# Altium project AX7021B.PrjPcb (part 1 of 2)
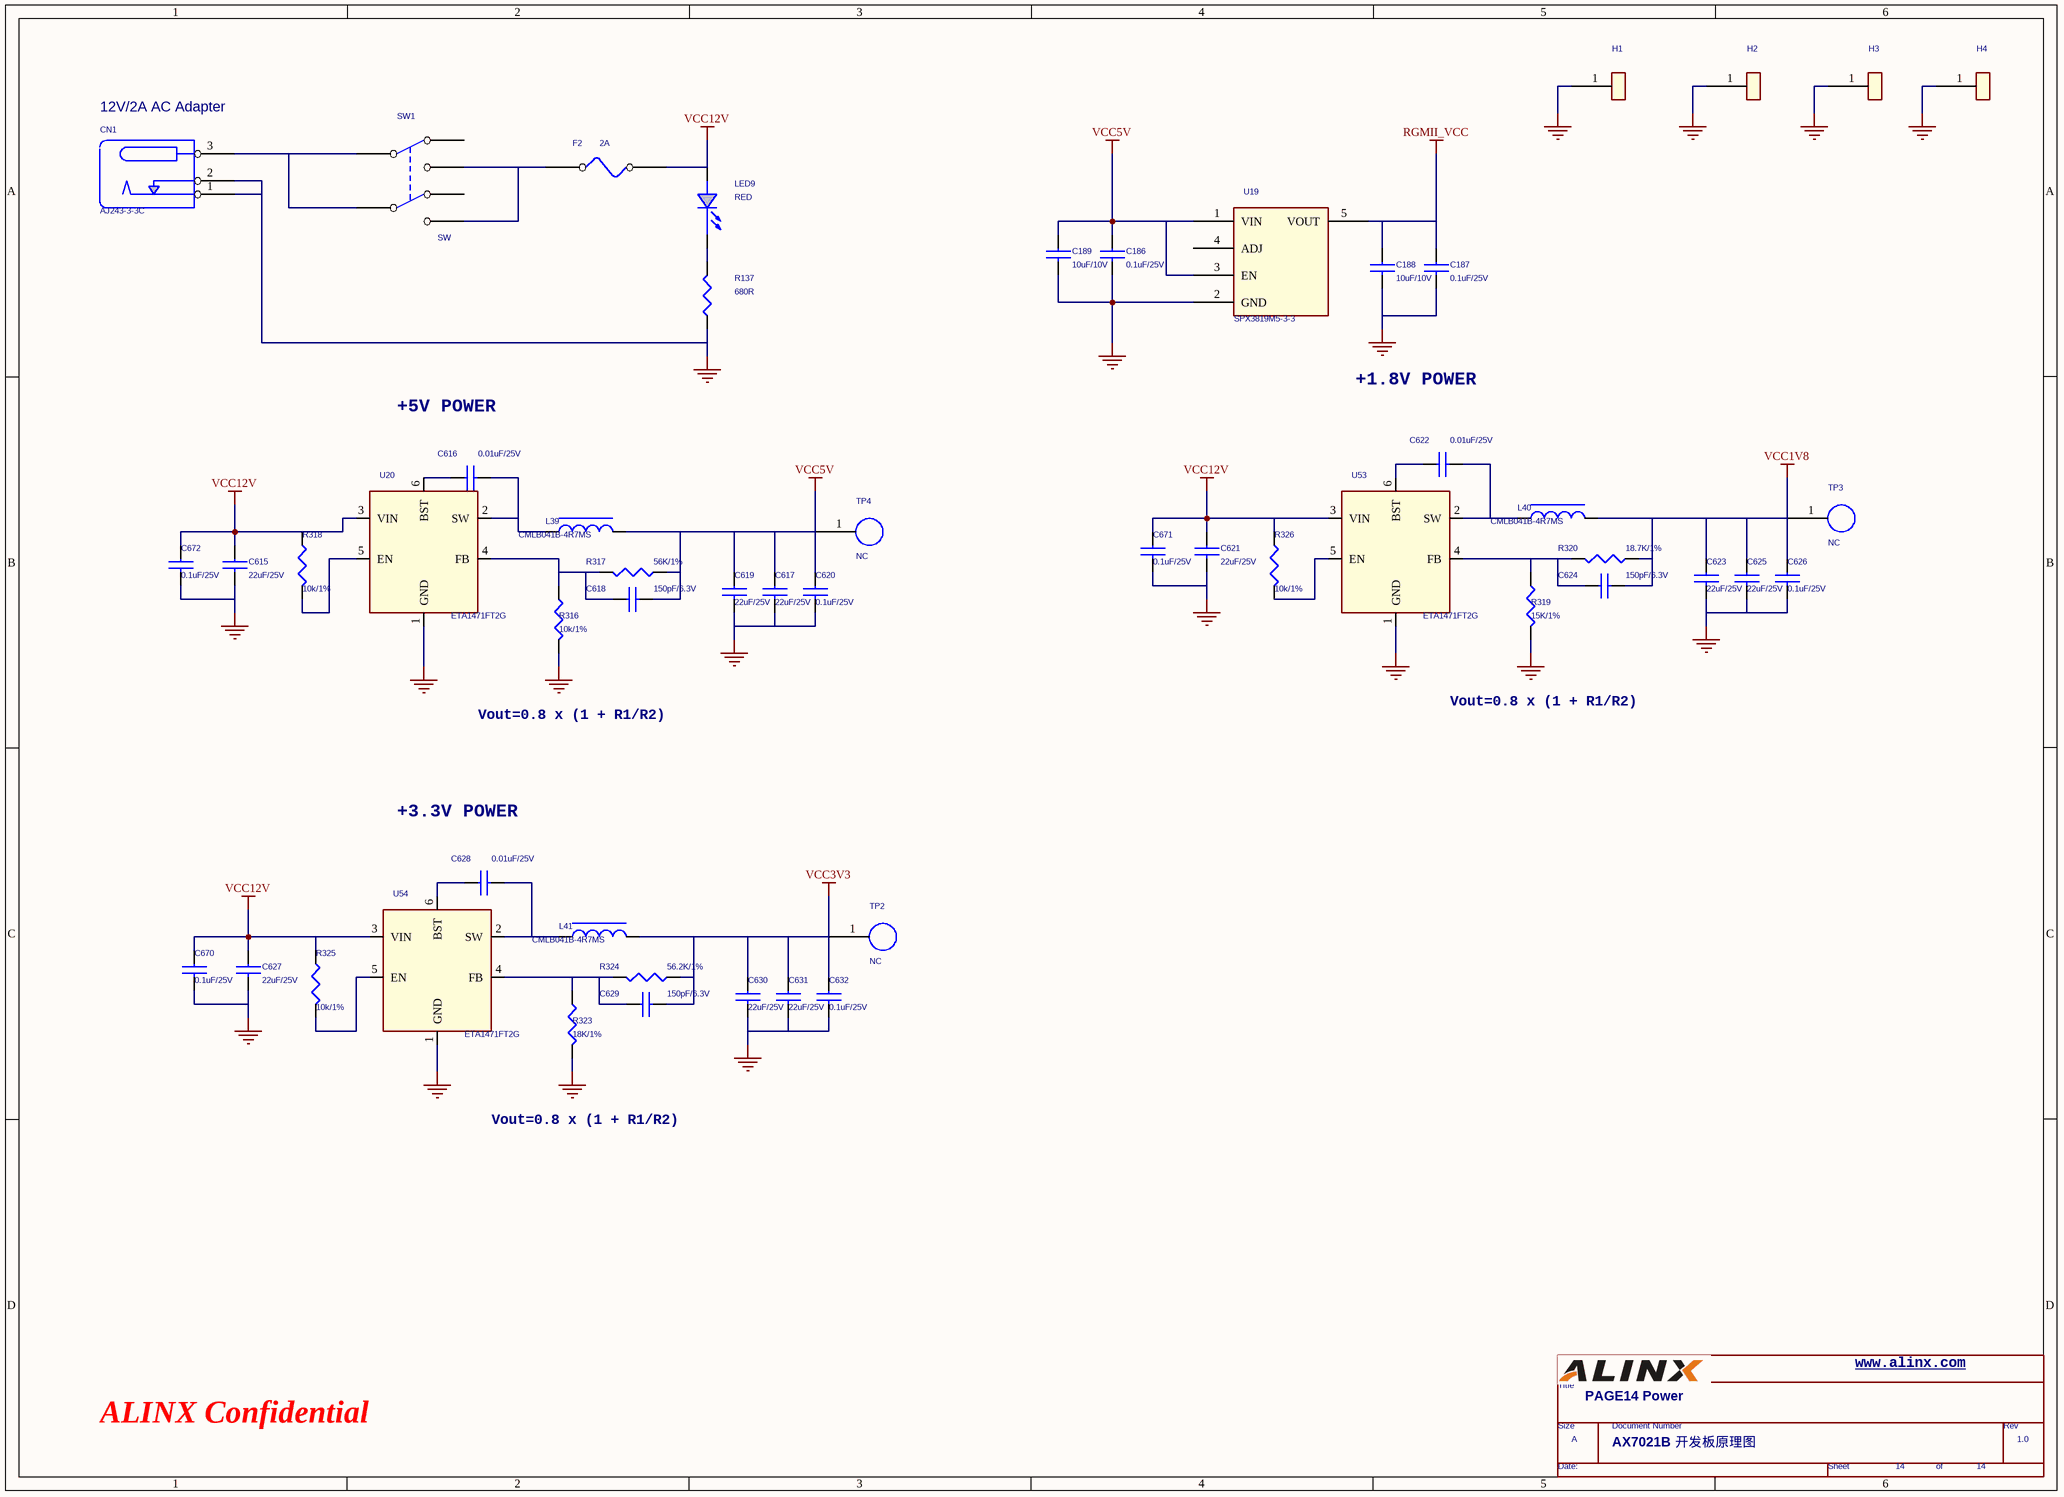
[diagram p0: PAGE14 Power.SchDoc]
14 sheets, 477 parts. Net scope: global (net labels, ports and power ports of the same name join across sheets).
Sheets:
  PAGE14 Power.SchDoc
  PAGE13 EX Connector.SchDoc
  PAGE12 KEY and LED.SchDoc
  PAGE11 PL Ethernet5.SchDoc
  PAGE10 PL Ethernet4.SchDoc
  PAGE09 PL Ethernet3.SchDoc
  PAGE08 PL Ethernet2.SchDoc
  PAGE07 HDMI OUT.SchDoc
  PAGE06 HOST USB X 4.SchDoc
  PAGE05 PS Ethernet1.SchDoc
  PAGE04 SD Card and UART.SchDoc
  PAGE03 JTAG.SchDoc
  PAGE02 Board Connector.SchDoc
  PAGE01 Block Diagram.SchDoc

## Sheet PAGE14 Power.SchDoc
size 386 x 279 mm

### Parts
(Parts that share a designator on the sheet are numbered #1, #2 ... from top to bottom, then left to right.)
*#1  Doc: AX7021B 开发板原理图  RevCode: 1.0  Title: PAGE14 Power  Page Size: A  Page Number: 14  (hidden comment: TitleBlock0)  (graphical)
C186  0.1uF/25V  [C0402]
C187  0.1uF/25V  [C0402]
C188  10uF/10V  [C0603]
C189  10uF/10V  [C0603]
C615  22uF/25V  [C0805]
C616  0.01uF/25V  [C0402]
C617  22uF/25V  [C0805]
C618  150pF/6.3V  [C0402]
C619  22uF/25V  [C0805]
C620  0.1uF/25V  [C0402]
C621  22uF/25V  [C0805]
C622  0.01uF/25V  [C0402]
C623  22uF/25V  [C0805]
C624  150pF/6.3V  [C0402]
C625  22uF/25V  [C0805]
C626  0.1uF/25V  [C0402]
C627  22uF/25V  [C0805]
C628  0.01uF/25V  [C0402]
C629  150pF/6.3V  [C0402]
C630  22uF/25V  [C0805]
C631  22uF/25V  [C0805]
C632  0.1uF/25V  [C0402]
C670  0.1uF/25V  [C0402]
C671  0.1uF/25V  [C0402]
C672  0.1uF/25V  [C0402]
CN1  AJ243-3-3C  [CN1-DCJACK]
F2  2A  [FUSE_1812]
H1  NC  [HOLE]  (value not drawn)
H2  NC  [HOLE]  (value not drawn)
H3  NC  [HOLE]  (value not drawn)
H4  NC  [HOLE]  (value not drawn)
L39  CMLB041B-4R7MS  [L4_4x4_2]
L40  CMLB041B-4R7MS  [L4_4x4_2]
L41  CMLB041B-4R7MS  [L4_4x4_2]
LED9  RED  [LED0805]
R137  680R  [R0402]
R316  10k/1%  [R0402]
R317  56K/1%  [R0402]
R318  10k/1%  [R0402]
R319  15K/1%  [R0402]
R320  18.7K/1%  [R0402]
R323  18K/1%  [R0402]
R324  56.2K/1%  [R0402]
R325  10k/1%  [R0402]
R326  10k/1%  [R0402]
SW1  SW  [KEY_DPDT]
TP2  NC  [TP_1-0]
TP3  NC  [TP_1-0]
TP4  NC  [TP_1-0]
U19  SPX3819M5-3-3  [SOT-23]
U20  ETA1471FT2G  [FCTSOT23-6]
U53  ETA1471FT2G  [FCTSOT23-6]
U54  ETA1471FT2G  [FCTSOT23-6]

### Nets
GND: C186.2 C187.2 C188.2 C189.2 C615.2 C617.2 C619.2 C620.2 C621.2 C623.2 C625.2 C626.2 C627.2 C630.2 C631.2 C632.2 C670.2 C671.2 C672.2 CN1.1 CN1.2 H1.1 H2.1 H3.1 H4.1 R137.1 R316.2 R319.2 R323.2 U19.2(GND) U20.1(GND) U53.1(GND) U54.1(GND)
RGMII_VCC: C187.1 C188.1 U19.5(VOUT)
VCC1V8: C623.1 C624.2 C625.1 C626.1 L40.2 R320.1 TP3.1
VCC3V3: C629.2 C630.1 C631.1 C632.1 L41.2 R324.1 TP2.1
VCC5V: C186.1 C189.1 C617.1 C618.2 C619.1 C620.1 L39.2 R317.1 TP4.1 U19.1(VIN) U19.3(EN)
VCC12V: C615.1 C621.1 C627.1 C670.1 C671.1 C672.1 F2.2 LED9.1(ANODE) R318.1 R325.1 R326.1 U20.3(VIN) U53.3(VIN) U54.3(VIN)
NetC616_1: C616.1 U20.6(BST)
NetC616_2: C616.2 L39.1 U20.2(SW)
NetC618_1: C618.1 R316.1 R317.2 U20.4(FB)
NetC622_1: C622.1 U53.6(BST)
NetC622_2: C622.2 L40.1 U53.2(SW)
NetC624_1: C624.1 R319.1 R320.2 U53.4(FB)
NetC628_1: C628.1 U54.6(BST)
NetC628_2: C628.2 L41.1 U54.2(SW)
NetC629_1: C629.1 R323.1 R324.2 U54.4(FB)
NetCN1_3: CN1.3 SW1.2(COMMON1) SW1.5(COMMON2)
NetF2_1: F2.1 SW1.3(NO1) SW1.6(NO2)
NetLED9_2: LED9.2(CATHODE) R137.2
NetR318_2: R318.2 U20.5(EN)
NetR325_2: R325.2 U54.5(EN)
NetR326_2: R326.2 U53.5(EN)

Not connected (* = marked no-connect by the designer): SW1 1(NC1) 4(NC2); U19 4(ADJ)

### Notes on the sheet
- (near CN1) 12V/2A AC Adapter
- +5V POWER
- +1.8V POWER
- Vout=0.8 x (1 + R1/R2)
- +3.3V POWER
- www.alinx.com
- ALINX Confidential

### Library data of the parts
C186-C189 C615-C619 C621-C625 C627-C631 = CAP NP: VA: 电容
C620 C626 C632 C670-C672 = C_1_Dup1: PART NUMBER: 1802-00187D; VA: 电容
CN1 = AJ243_0: VA: 黑色圆头电源插件
F2 = FUSE: VA: 自恢复保险丝
H1-H4 = TEST POINT_Dup1
L39 L40 = CHOKE RF-IRON_0: Ordering P/N: LPS3015-222MLC; ID: 0101130006; MFG: Coilcraft; VA: 电感
L41 = CHOKE RF-IRON_0: VA: 电感; MFG: Coilcraft; MFG PN: LPS3015-222MLC; ID: 0101130006
LED9 = LED: VA: 红色LED灯
R137 R316 R317 R319 R320 R323 R324 = RESISTOR: VA: 电阻
R318 R325 R326 = 100K: 5%; Part Number: RC0402JR-07100KL; Manufacturer: YAGEO; VA: 电阻
SW1 = SW KEY-DPDT: VA: 6脚电源开关
TP2-TP4 = TP: Test point; Part Number: NC_TP
U19 = SPX3819M5-2-5: VA: 电源芯片
U20 U53 U54 = ETA1471FT2G: VA: 芯片

## Sheet PAGE13 EX Connector.SchDoc
size 386 x 279 mm
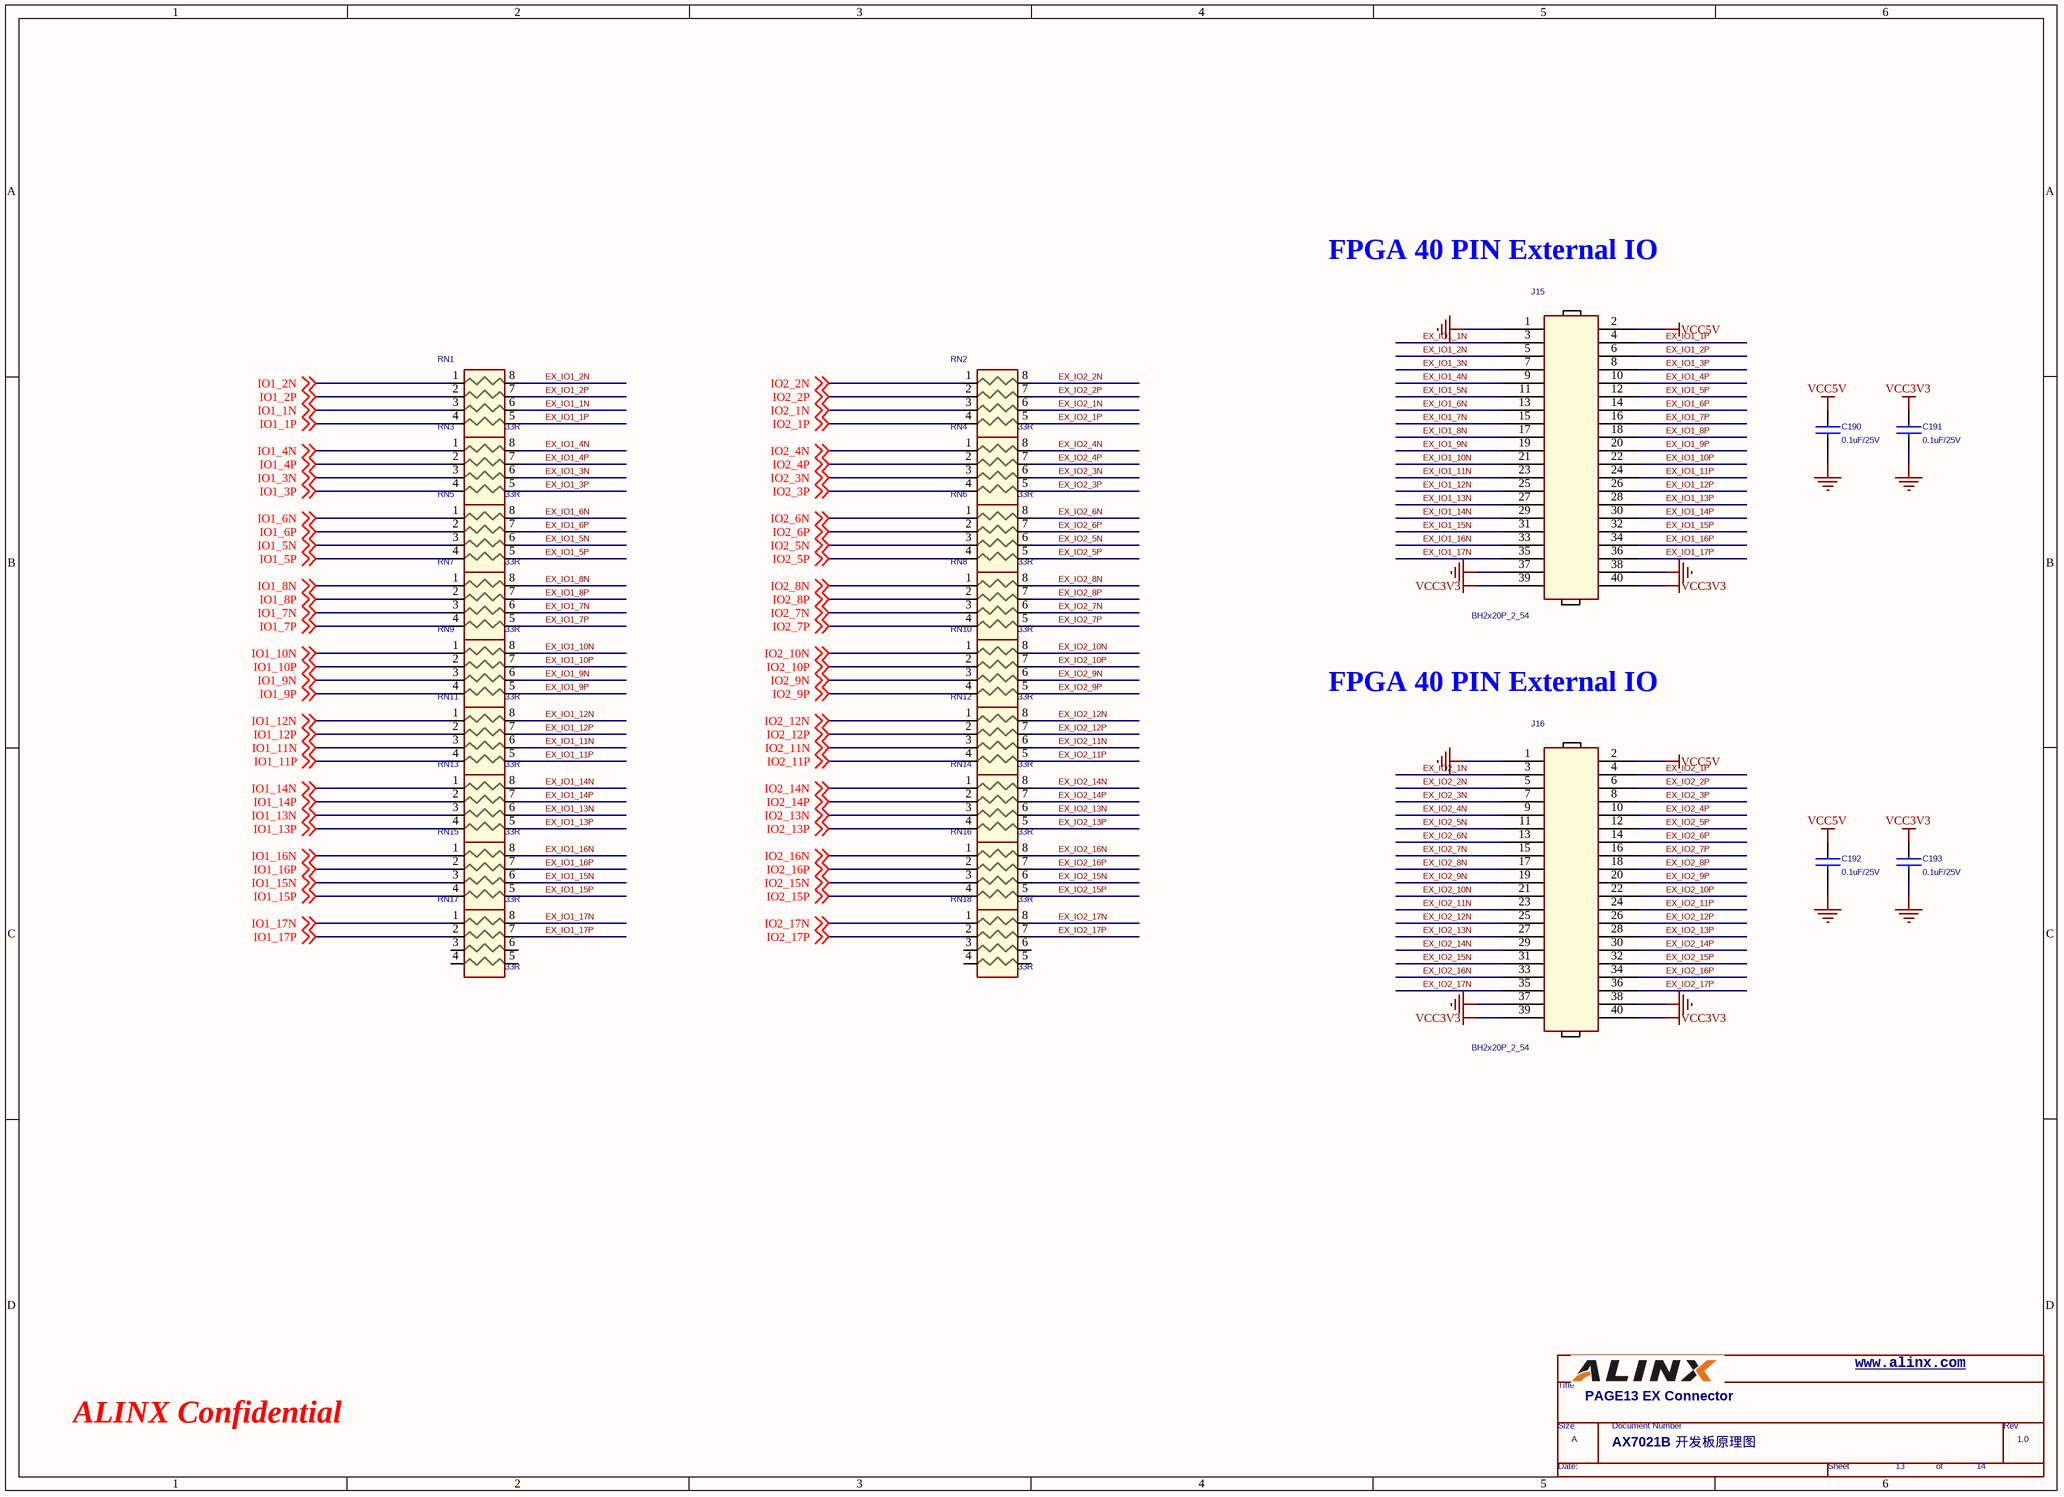
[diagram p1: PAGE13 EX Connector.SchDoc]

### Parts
(Parts that share a designator on the sheet are numbered #1, #2 ... from top to bottom, then left to right.)
*#2  Doc: AX7021B 开发板原理图  RevCode: 1.0  Title: PAGE13 EX Connector  Page Size: A  Page Number: 13  Page Count: 14  (hidden comment: TitleBlock0)  (graphical)
C190  0.1uF/25V  [C0402]
C191  0.1uF/25V  [C0402]
C192  0.1uF/25V  [C0402]
C193  0.1uF/25V  [C0402]
J15  BH2x20P_2_54  [IDC-40J]
J16  BH2x20P_2_54  [IDC-40J]
RN1  33R  [RN-8P]
RN2  33R  [RN-8P]
RN3  33R  [RN-8P]
RN4  33R  [RN-8P]
RN5  33R  [RN-8P]
RN6  33R  [RN-8P]
RN7  33R  [RN-8P]
RN8  33R  [RN-8P]
RN9  33R  [RN-8P]
RN10  33R  [RN-8P]
RN11  33R  [RN-8P]
RN12  33R  [RN-8P]
RN13  33R  [RN-8P]
RN14  33R  [RN-8P]
RN15  33R  [RN-8P]
RN16  33R  [RN-8P]
RN17  33R  [RN-8P]
RN18  33R  [RN-8P]

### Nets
GND: C190.2 C191.2 C192.2 C193.2 J15.1 J15.37 J15.38 J16.1 J16.37 J16.38
VCC3V3: C191.1 C193.1 J15.39 J15.40 J16.39 J16.40
VCC5V: C190.1 C192.1 J15.2 J16.2
EX_IO1_1N: J15.3 RN1.6
EX_IO1_1P: J15.4 RN1.5
EX_IO1_2N: J15.5 RN1.8
EX_IO1_2P: J15.6 RN1.7
EX_IO1_3N: J15.7 RN3.6
EX_IO1_3P: J15.8 RN3.5
EX_IO1_4N: J15.9 RN3.8
EX_IO1_4P: J15.10 RN3.7
EX_IO1_5N: J15.11 RN5.6
EX_IO1_5P: J15.12 RN5.5
EX_IO1_6N: J15.13 RN5.8
EX_IO1_6P: J15.14 RN5.7
EX_IO1_7N: J15.15 RN7.6
EX_IO1_7P: J15.16 RN7.5
EX_IO1_8N: J15.17 RN7.8
EX_IO1_8P: J15.18 RN7.7
EX_IO1_9N: J15.19 RN9.6
EX_IO1_9P: J15.20 RN9.5
EX_IO1_10N: J15.21 RN9.8
EX_IO1_10P: J15.22 RN9.7
EX_IO1_11N: J15.23 RN11.6
EX_IO1_11P: J15.24 RN11.5
EX_IO1_12N: J15.25 RN11.8
EX_IO1_12P: J15.26 RN11.7
EX_IO1_13N: J15.27 RN13.6
EX_IO1_13P: J15.28 RN13.5
EX_IO1_14N: J15.29 RN13.8
EX_IO1_14P: J15.30 RN13.7
EX_IO1_15N: J15.31 RN15.6
EX_IO1_15P: J15.32 RN15.5
EX_IO1_16N: J15.33 RN15.8
EX_IO1_16P: J15.34 RN15.7
EX_IO1_17N: J15.35 RN17.8
EX_IO1_17P: J15.36 RN17.7
EX_IO2_1N: J16.3 RN2.6
EX_IO2_1P: J16.4 RN2.5
EX_IO2_2N: J16.5 RN2.8
EX_IO2_2P: J16.6 RN2.7
EX_IO2_3N: J16.7 RN4.6
EX_IO2_3P: J16.8 RN4.5
EX_IO2_4N: J16.9 RN4.8
EX_IO2_4P: J16.10 RN4.7
EX_IO2_5N: J16.11 RN6.6
EX_IO2_5P: J16.12 RN6.5
EX_IO2_6N: J16.13 RN6.8
EX_IO2_6P: J16.14 RN6.7
EX_IO2_7N: J16.15 RN8.6
EX_IO2_7P: J16.16 RN8.5
EX_IO2_8N: J16.17 RN8.8
EX_IO2_8P: J16.18 RN8.7
EX_IO2_9N: J16.19 RN10.6
EX_IO2_9P: J16.20 RN10.5
EX_IO2_10N: J16.21 RN10.8
EX_IO2_10P: J16.22 RN10.7
EX_IO2_11N: J16.23 RN12.6
EX_IO2_11P: J16.24 RN12.5
EX_IO2_12N: J16.25 RN12.8
EX_IO2_12P: J16.26 RN12.7
EX_IO2_13N: J16.27 RN14.6
EX_IO2_13P: J16.28 RN14.5
EX_IO2_14N: J16.29 RN14.8
EX_IO2_14P: J16.30 RN14.7
EX_IO2_15N: J16.31 RN16.6
EX_IO2_15P: J16.32 RN16.5
EX_IO2_16N: J16.33 RN16.8
EX_IO2_16P: J16.34 RN16.7
EX_IO2_17N: J16.35 RN18.8
EX_IO2_17P: J16.36 RN18.7
IO1_1N: RN1.3 ; off-sheet IO1_1N
IO1_1P: RN1.4 ; off-sheet IO1_1P
IO1_2N: RN1.1 ; off-sheet IO1_2N
IO1_2P: RN1.2 ; off-sheet IO1_2P
IO1_3N: RN3.3 ; off-sheet IO1_3N
IO1_3P: RN3.4 ; off-sheet IO1_3P
IO1_4N: RN3.1 ; off-sheet IO1_4N
IO1_4P: RN3.2 ; off-sheet IO1_4P
IO1_5N: RN5.3 ; off-sheet IO1_5N
IO1_5P: RN5.4 ; off-sheet IO1_5P
IO1_6N: RN5.1 ; off-sheet IO1_6N
IO1_6P: RN5.2 ; off-sheet IO1_6P
IO1_7N: RN7.3 ; off-sheet IO1_7N
IO1_7P: RN7.4 ; off-sheet IO1_7P
IO1_8N: RN7.1 ; off-sheet IO1_8N
IO1_8P: RN7.2 ; off-sheet IO1_8P
IO1_9N: RN9.3 ; off-sheet IO1_9N
IO1_9P: RN9.4 ; off-sheet IO1_9P
IO1_10N: RN9.1 ; off-sheet IO1_10N
IO1_10P: RN9.2 ; off-sheet IO1_10P
IO1_11N: RN11.3 ; off-sheet IO1_11N
IO1_11P: RN11.4 ; off-sheet IO1_11P
IO1_12N: RN11.1 ; off-sheet IO1_12N
IO1_12P: RN11.2 ; off-sheet IO1_12P
IO1_13N: RN13.3 ; off-sheet IO1_13N
IO1_13P: RN13.4 ; off-sheet IO1_13P
IO1_14N: RN13.1 ; off-sheet IO1_14N
IO1_14P: RN13.2 ; off-sheet IO1_14P
IO1_15N: RN15.3 ; off-sheet IO1_15N
IO1_15P: RN15.4 ; off-sheet IO1_15P
IO1_16N: RN15.1 ; off-sheet IO1_16N
IO1_16P: RN15.2 ; off-sheet IO1_16P
IO1_17N: RN17.1 ; off-sheet IO1_17N
IO1_17P: RN17.2 ; off-sheet IO1_17P
IO2_1N: RN2.3 ; off-sheet IO2_1N
IO2_1P: RN2.4 ; off-sheet IO2_1P
IO2_2N: RN2.1 ; off-sheet IO2_2N
IO2_2P: RN2.2 ; off-sheet IO2_2P
IO2_3N: RN4.3 ; off-sheet IO2_3N
IO2_3P: RN4.4 ; off-sheet IO2_3P
IO2_4N: RN4.1 ; off-sheet IO2_4N
IO2_4P: RN4.2 ; off-sheet IO2_4P
IO2_5N: RN6.3 ; off-sheet IO2_5N
IO2_5P: RN6.4 ; off-sheet IO2_5P
IO2_6N: RN6.1 ; off-sheet IO2_6N
IO2_6P: RN6.2 ; off-sheet IO2_6P
IO2_7N: RN8.3 ; off-sheet IO2_7N
IO2_7P: RN8.4 ; off-sheet IO2_7P
IO2_8N: RN8.1 ; off-sheet IO2_8N
IO2_8P: RN8.2 ; off-sheet IO2_8P
IO2_9N: RN10.3 ; off-sheet IO2_9N
IO2_9P: RN10.4 ; off-sheet IO2_9P
IO2_10N: RN10.1 ; off-sheet IO2_10N
IO2_10P: RN10.2 ; off-sheet IO2_10P
IO2_11N: RN12.3 ; off-sheet IO2_11N
IO2_11P: RN12.4 ; off-sheet IO2_11P
IO2_12N: RN12.1 ; off-sheet IO2_12N
IO2_12P: RN12.2 ; off-sheet IO2_12P
IO2_13N: RN14.3 ; off-sheet IO2_13N
IO2_13P: RN14.4 ; off-sheet IO2_13P
IO2_14N: RN14.1 ; off-sheet IO2_14N
IO2_14P: RN14.2 ; off-sheet IO2_14P
IO2_15N: RN16.3 ; off-sheet IO2_15N
IO2_15P: RN16.4 ; off-sheet IO2_15P
IO2_16N: RN16.1 ; off-sheet IO2_16N
IO2_16P: RN16.2 ; off-sheet IO2_16P
IO2_17N: RN18.1 ; off-sheet IO2_17N
IO2_17P: RN18.2 ; off-sheet IO2_17P

Not connected (* = marked no-connect by the designer): RN17 3 4 5 6; RN18 3 4 5 6

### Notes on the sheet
- FPGA 40 PIN External IO
- www.alinx.com
- ALINX Confidential

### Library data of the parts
C190-C193 = CAP NP: VA: 电容
J15 J16 = HEADER 20x2/M: VA: 2x20P简牛座
RN1-RN18 = RESARR_IS_4/SM: VA: 排阻

## Sheet PAGE12 KEY and LED.SchDoc
size 386 x 279 mm
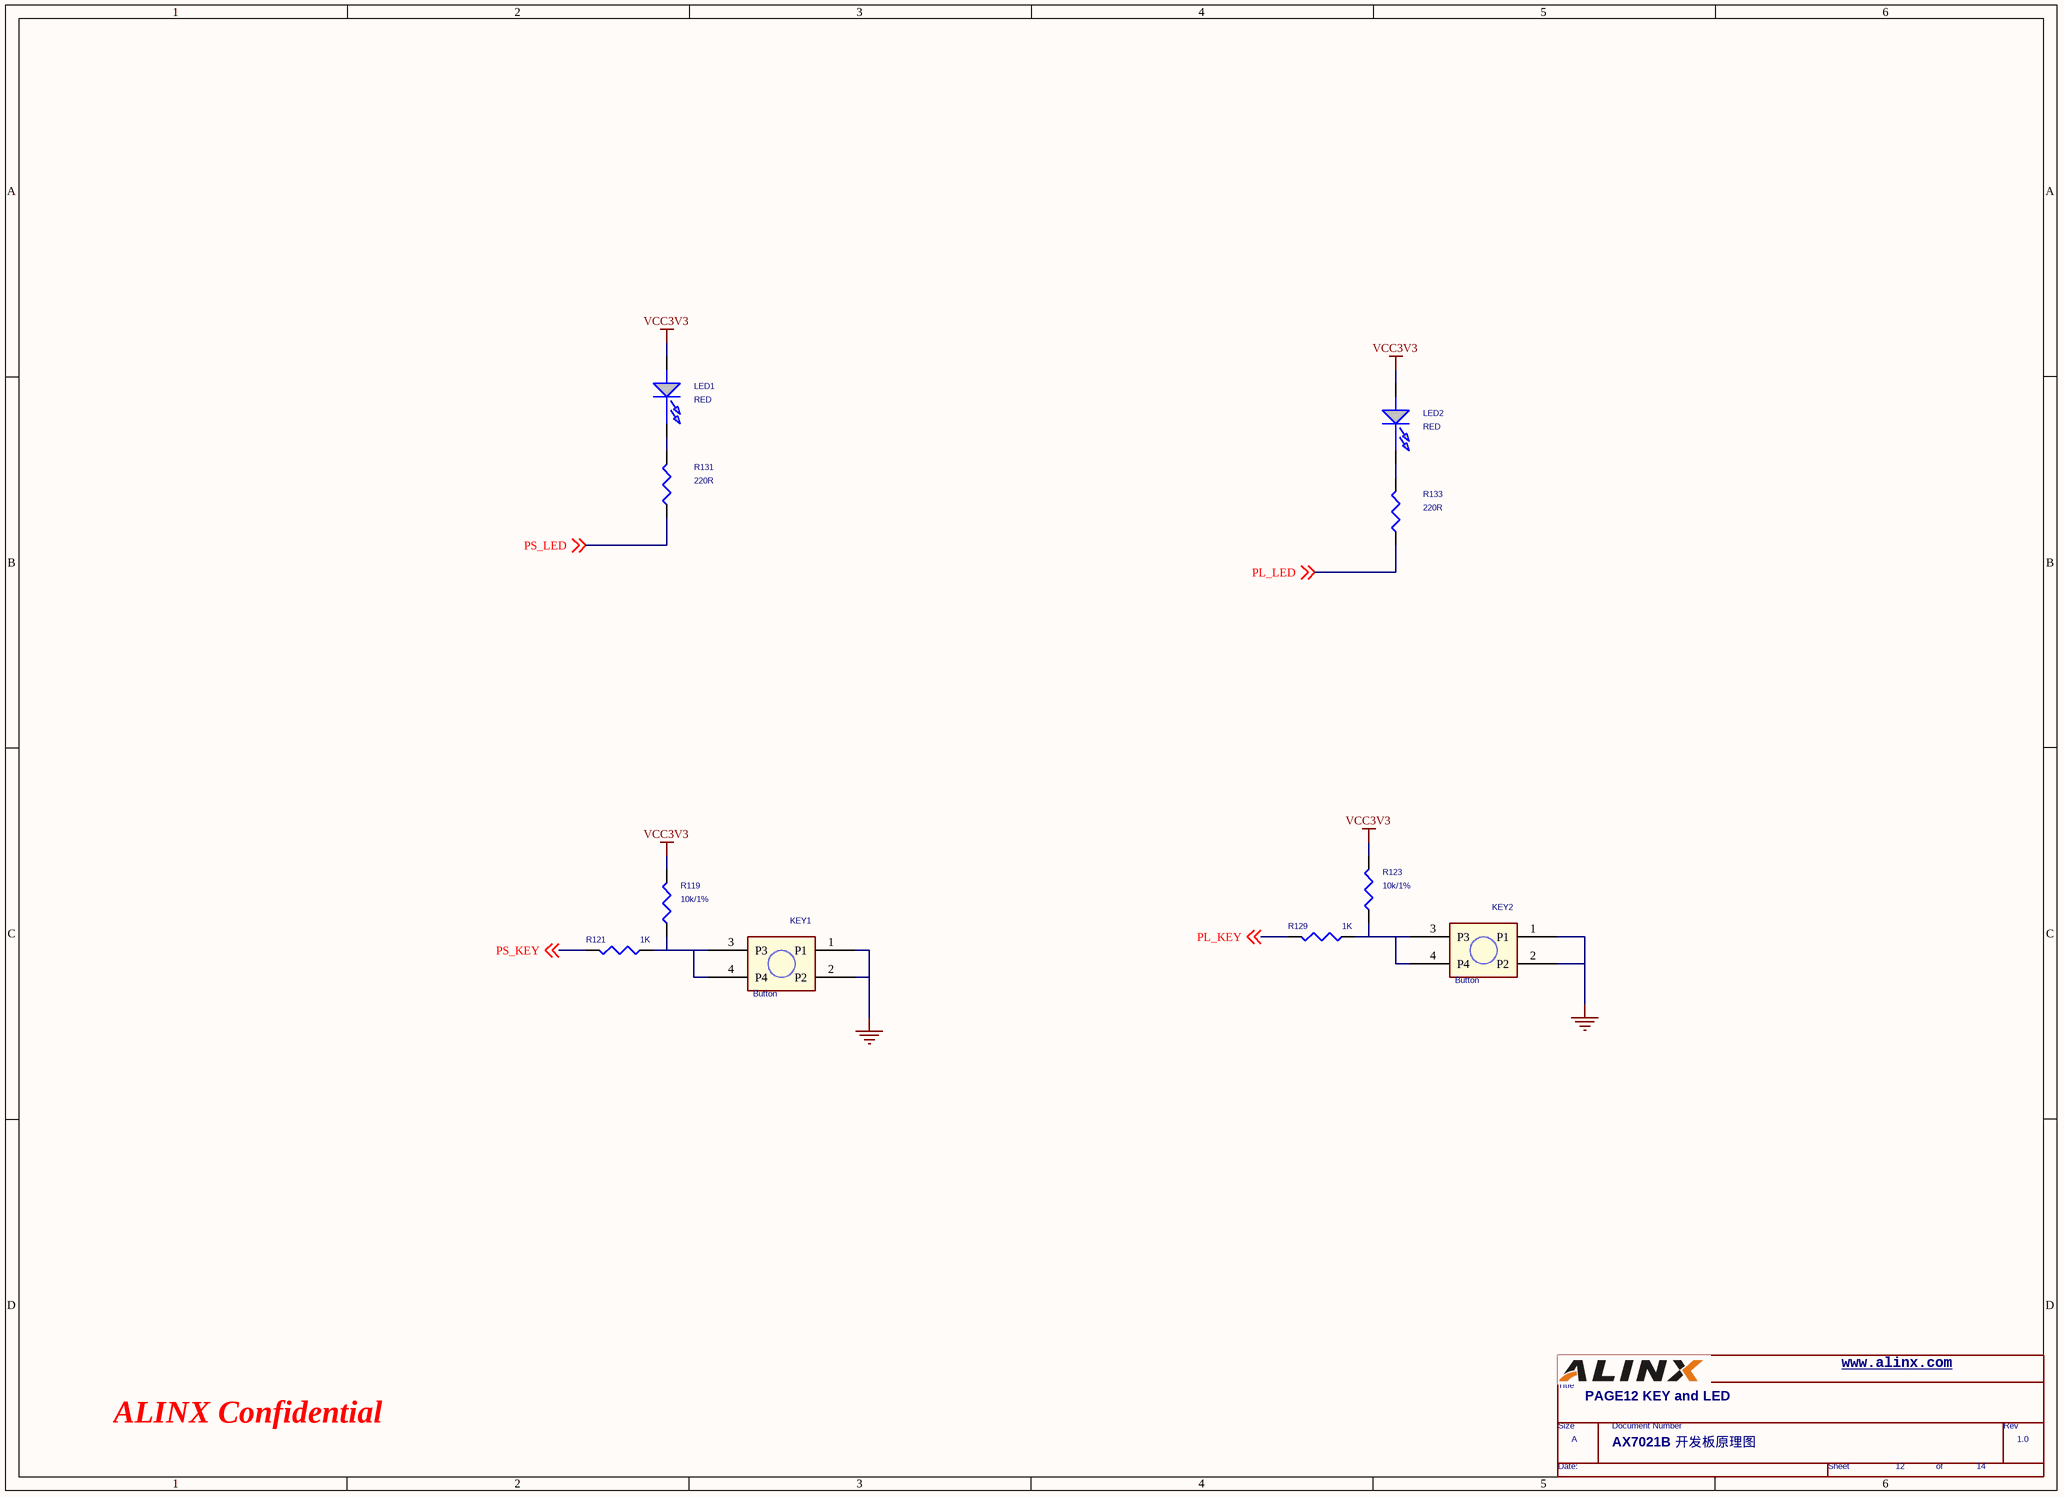
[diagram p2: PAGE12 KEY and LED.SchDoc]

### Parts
(Parts that share a designator on the sheet are numbered #1, #2 ... from top to bottom, then left to right.)
*#3  Doc: AX7021B 开发板原理图  RevCode: 1.0  Title: PAGE12 KEY and LED  Page Size: A  Page Number: 12  Page Count: 14  (hidden comment: TitleBlock0)  (graphical)
KEY1  Button  [KEY_4x4x1_5]
KEY2  Button  [KEY_4x4x1_5]
LED1  RED  [LED0805]
LED2  RED  [LED0805]
R119  10k/1%  [R0402]
R121  1K  [R0402]
R123  10k/1%  [R0402]
R129  1K  [R0402]
R131  220R  [R0402]
R133  220R  [R0402]

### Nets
GND: KEY1.1(P1) KEY1.2(P2) KEY2.1(P1) KEY2.2(P2)
VCC3V3: LED1.1(ANODE) LED2.1(ANODE) R119.2 R123.2
PL_KEY: R129.2 ; off-sheet PL_KEY
PL_LED: R133.1 ; off-sheet PL_LED
PS_KEY: R121.2 ; off-sheet PS_KEY
PS_LED: R131.1 ; off-sheet PS_LED
NetKEY1_3: KEY1.3(P3) KEY1.4(P4) R119.1 R121.1
NetKEY2_3: KEY2.3(P3) KEY2.4(P4) R123.1 R129.1
NetLED1_2: LED1.2(CATHODE) R131.2
NetLED2_2: LED2.2(CATHODE) R133.2

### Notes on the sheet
- www.alinx.com
- ALINX Confidential

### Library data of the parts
KEY1 KEY2 = Button_0: VA: 4脚按键
LED1 LED2 = LN211WP: VA: 红色LED灯
R119 R121 R123 R129 R131 R133 = RESISTOR: VA: 电阻

## Sheet PAGE11 PL Ethernet5.SchDoc
size 386 x 279 mm
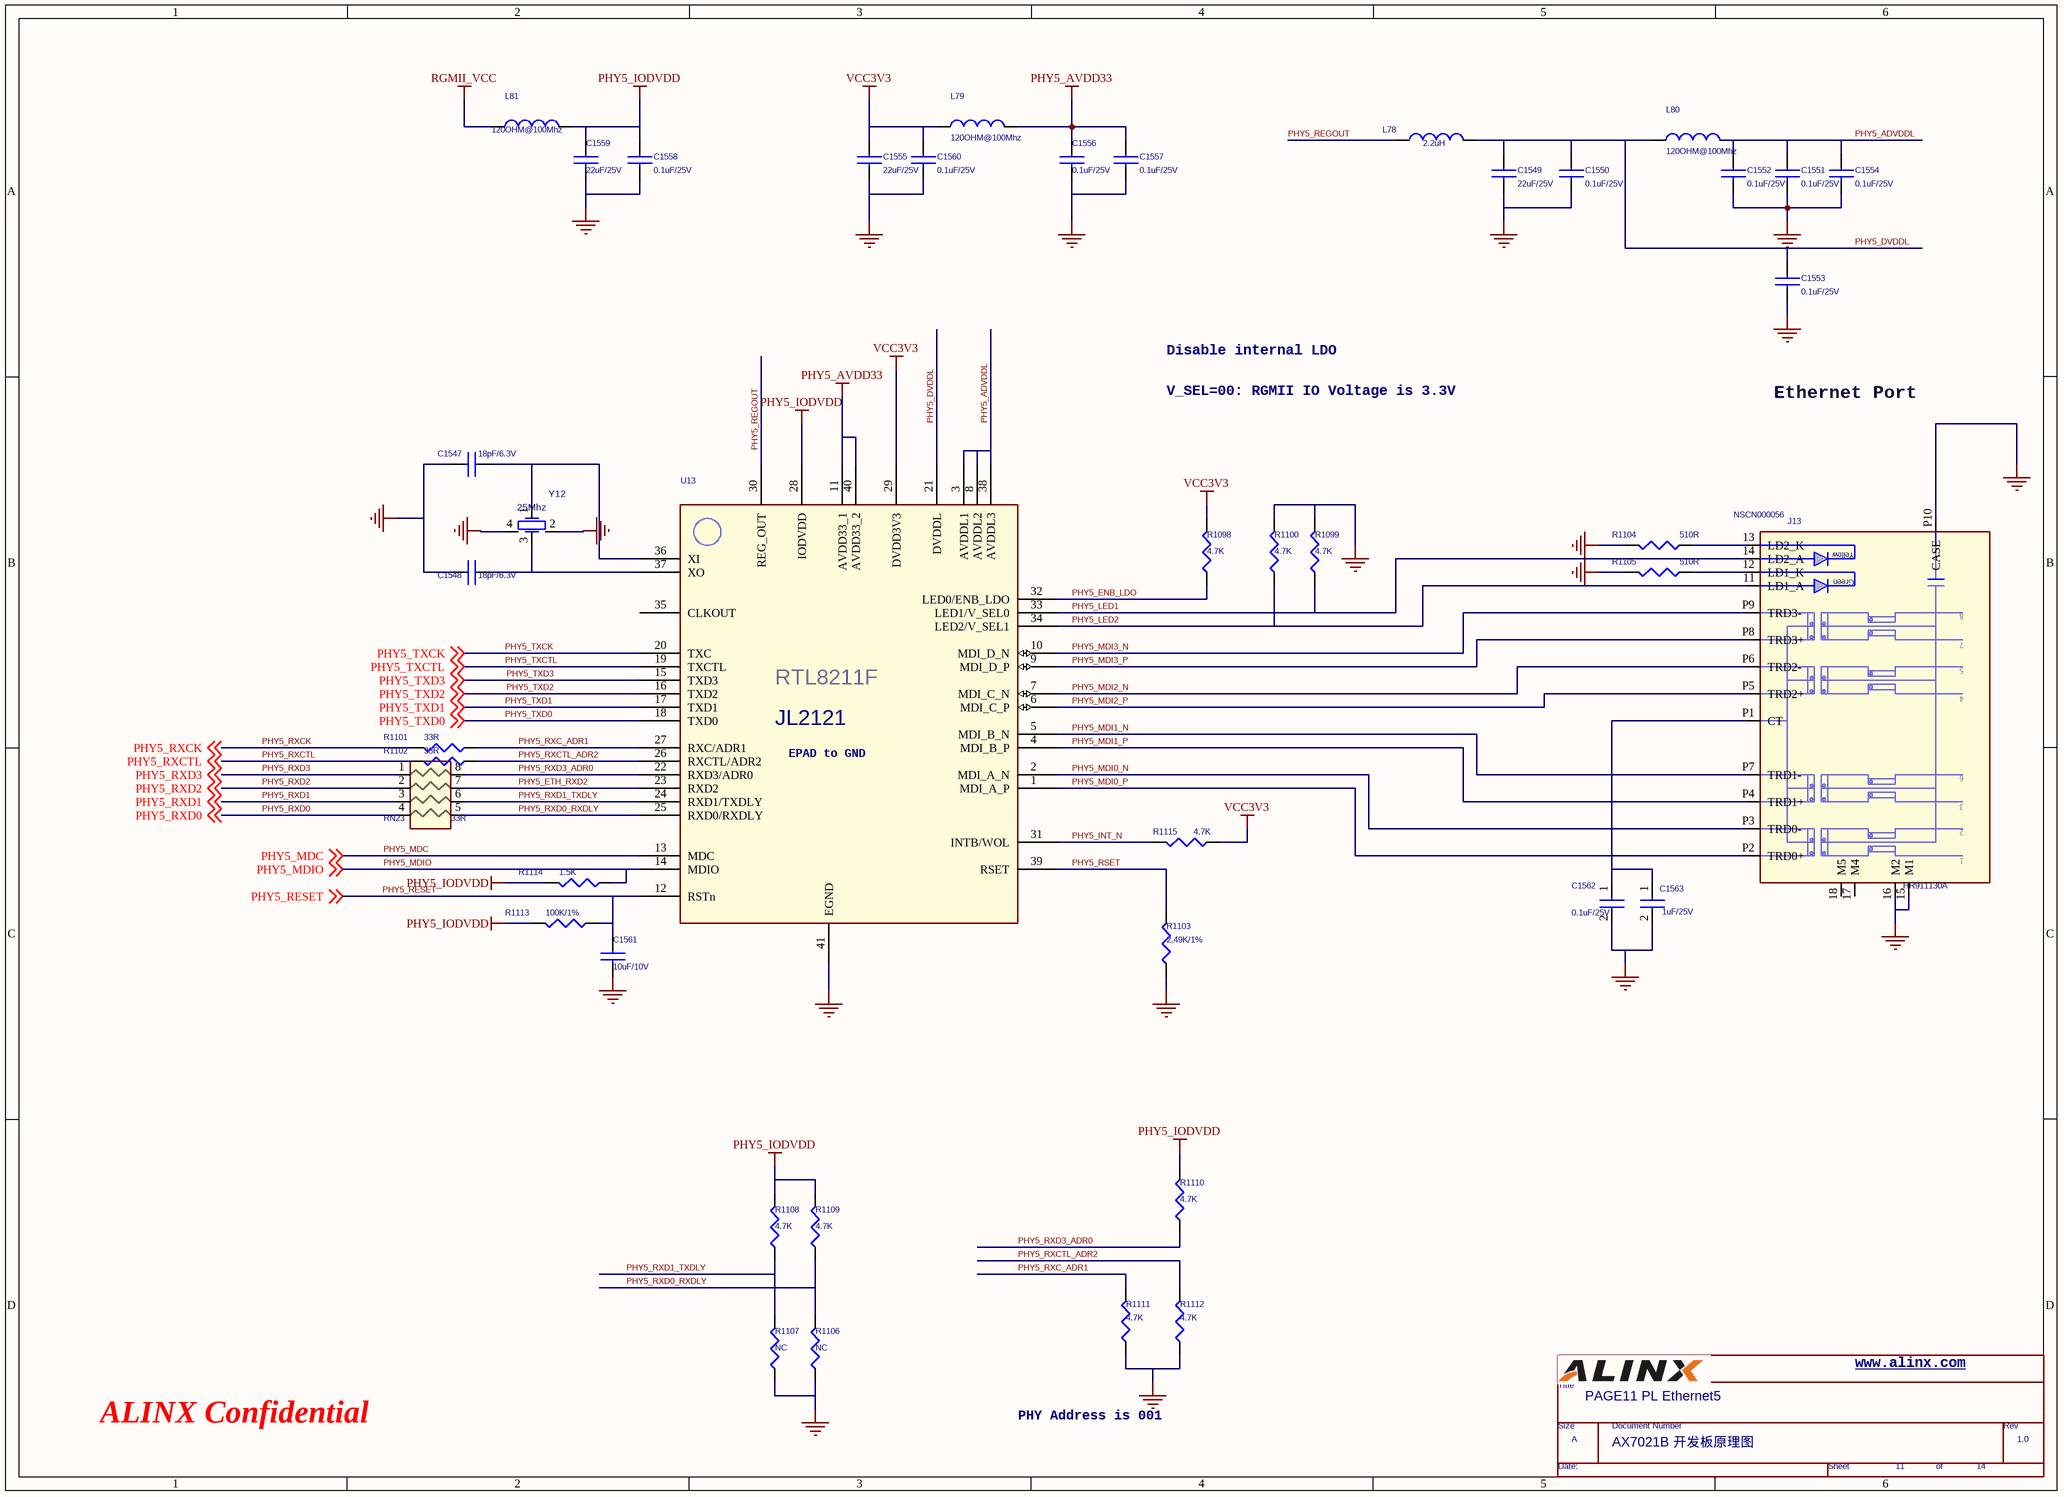
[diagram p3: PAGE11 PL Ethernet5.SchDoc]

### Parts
(Parts that share a designator on the sheet are numbered #1, #2 ... from top to bottom, then left to right.)
*#4  Doc: AX7021B 开发板原理图  RevCode: 1.0  Title: PAGE11 PL Ethernet5  Page Size: A  Page Number: 11  Page Count: 14  (hidden comment: TitleBlock0)  (graphical)
C1547  18pF/6.3V  [C0402]
C1548  18pF/6.3V  [C0402]
C1549  22uF/25V  [C0805]
C1550  0.1uF/25V  [C0402]
C1551  0.1uF/25V  [C0402]
C1552  0.1uF/25V  [C0402]
C1553  0.1uF/25V  [C0402]
C1554  0.1uF/25V  [C0402]
C1555  22uF/25V  [C0805]
C1556  0.1uF/25V  [C0402]
C1557  0.1uF/25V  [C0402]
C1558  0.1uF/25V  [C0402]
C1559  22uF/25V  [C0805]
C1560  0.1uF/25V  [C0402]
C1561  10uF/10V  [C0603]
C1562  0.1uF/25V  [C0402]
C1563  1uF/25V  [C0402]
J13  HR911130A  CODE: NSCN000056  [GE_RJ45]
L78  2.2uH  [LVS303010]
L79  120OHM@100Mhz  [L0603]
L80  120OHM@100Mhz  [L0603]
L81  120OHM@100Mhz  [L0603]
R1098  4.7K  [R0402]
R1099  4.7K  [R0402]
R1100  4.7K  [R0402]
R1101  33R  [R0402]
R1102  33R  [R0402]
R1103  2.49K/1%  [R0402]
R1104  510R  [R0402]
R1105  510R  [R0402]
R1106  NC  [R0402]
R1107  NC  [R0402]
R1108  4.7K  [R0402]
R1109  4.7K  [R0402]
R1110  4.7K  [R0402]
R1111  4.7K  [R0402]
R1112  4.7K  [R0402]
R1113  100K/1%  [R0402]
R1114  1.5K  [R0402]
R1115  4.7K  [R0402]
RN23  33R  [RN-8P]
U13  JL2121-N040I  [QFN40]  (value not drawn)
Y12  25Mhz  [OSC3225]

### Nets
GND: C1547.2 C1548.2 C1549.2 C1550.2 C1551.2 C1552.2 C1553.2 C1554.2 C1555.2 C1556.2 C1557.2 C1558.2 C1559.2 C1560.2 C1561.2 C1562.2 C1563.2 J13.15(M1) J13.16(M2) J13.P10(CASE) R1099.2 R1100.2 R1103.1 R1104.2 R1105.2 R1106.1 R1107.1 R1111.1 R1112.1 U13.41(EGND) Y12.2 Y12.4
PHY5_AVDD33: C1556.1 C1557.1 L79.2 U13.11(AVDD33_1) U13.40(AVDD33_2)
PHY5_IODVDD: C1558.1 C1559.1 L81.2 R1108.2 R1109.2 R1110.2 R1113.2 R1114.2 U13.28(IODVDD)
RGMII_VCC: L81.1
VCC3V3: C1555.1 C1560.1 L79.1 R1098.2 R1115.1 U13.29(DVDD3V3)
PHY5_ADVDDL: C1551.1 C1552.1 C1554.1 L80.2 U13.3(AVDDL1) U13.8(AVDDL2) U13.38(AVDDL3)
PHY5_DVDDL: C1549.1 C1550.1 C1553.1 L78.2 L80.1 U13.21(DVDDL)
PHY5_ENB_LDO: R1098.1 U13.32(LED0/ENB_LDO)
PHY5_ETH_RXD2: RN23.7 U13.23(RXD2)
PHY5_INT_N: R1115.2 U13.31(INTB/WOL)
PHY5_LED1: J13.14(LD2_A) R1099.1 U13.33(LED1/V_SEL0)
PHY5_LED2: J13.11(LD1_A) R1100.1 U13.34(LED2/V_SEL1)
PHY5_MDC: U13.13(MDC) ; off-sheet PHY5_MDC
PHY5_MDI0_N: J13.P3(TRD0-) U13.2(MDI_A_N)
PHY5_MDI0_P: J13.P2(TRD0+) U13.1(MDI_A_P)
PHY5_MDI1_N: J13.P7(TRD1-) U13.5(MDI_B_N)
PHY5_MDI1_P: J13.P4(TRD1+) U13.4(MDI_B_P)
PHY5_MDI2_N: J13.P6(TRD2-) U13.7(MDI_C_N)
PHY5_MDI2_P: J13.P5(TRD2+) U13.6(MDI_C_P)
PHY5_MDI3_N: J13.P9(TRD3-) U13.10(MDI_D_N)
PHY5_MDI3_P: J13.P8(TRD3+) U13.9(MDI_D_P)
PHY5_MDIO: R1114.1 U13.14(MDIO) ; off-sheet PHY5_MDIO
PHY5_REGOUT: L78.1 U13.30(REG_OUT)
PHY5_RESET: C1561.1 R1113.1 U13.12(RSTn) ; off-sheet PHY5_RESET
PHY5_RSET: R1103.2 U13.39(RSET)
PHY5_RXC_ADR1: R1101.1 R1111.2 U13.27(RXC/ADR1)
PHY5_RXCK: R1101.2 ; off-sheet PHY5_RXCK
PHY5_RXCTL: R1102.2 ; off-sheet PHY5_RXCTL
PHY5_RXCTL_ADR2: R1102.1 R1112.2 U13.26(RXCTL/ADR2)
PHY5_RXD0: RN23.4 ; off-sheet PHY5_RXD0
PHY5_RXD0_RXDLY: R1106.2 R1109.1 RN23.5 U13.25(RXD0/RXDLY)
PHY5_RXD1: RN23.3 ; off-sheet PHY5_RXD1
PHY5_RXD1_TXDLY: R1107.2 R1108.1 RN23.6 U13.24(RXD1/TXDLY)
PHY5_RXD2: RN23.2 ; off-sheet PHY5_RXD2
PHY5_RXD3: RN23.1 ; off-sheet PHY5_RXD3
PHY5_RXD3_ADR0: R1110.1 RN23.8 U13.22(RXD3/ADR0)
PHY5_TXCK: U13.20(TXC) ; off-sheet PHY5_TXCK
PHY5_TXCTL: U13.19(TXCTL) ; off-sheet PHY5_TXCTL
PHY5_TXD0: U13.18(TXD0) ; off-sheet PHY5_TXD0
PHY5_TXD1: U13.17(TXD1) ; off-sheet PHY5_TXD1
PHY5_TXD2: U13.16(TXD2) ; off-sheet PHY5_TXD2
PHY5_TXD3: U13.15(TXD3) ; off-sheet PHY5_TXD3
NetC1547_1: C1547.1 U13.36(XI) Y12.1
NetC1548_1: C1548.1 U13.37(XO) Y12.3
NetC1562_1: C1562.1 C1563.1 J13.P1(CT)
NetJ13_12: J13.12(LD1_K) R1105.1
NetJ13_13: J13.13(LD2_K) R1104.1

Not connected (* = marked no-connect by the designer): J13 17(M4) 18(M5); U13 35(CLKOUT)

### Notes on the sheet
- Disable internal LDO
- V_SEL=00: RGMII IO Voltage is 3.3V
- Ethernet Port
- www.alinx.com
- ALINX Confidential
- PHY Address is 001

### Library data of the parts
C1547-C1561 = CAP NP: VA: 电容
C1562 = CAP_3: MLCC,0402,GRM155R61A104KA01D(RoHS)(HF),0.1UF 10V X5R +-10%,MURATA; PEGATRON_PART_NUMBER: 1A20-009R600; Manufacturer's Part Number: GRM155R61A104KA01D(GRM36X5R104K10)(RoHS); FULL_LEAD_TIME: 42; ORDER_SEQ: 6; PPL_FLAG: X; Life_Cycle_Flag: 4; Item_Priority: B; AP: Y; CompType: 刚玻/秖玻; VA: 电容
C1563 = CAP_3: MLCC,0603,GRM188R61A105KA61D(RoHS),1UF 10V X5R +-10%,MURATA; PEGATRON_PART_NUMBER: 1A30-00W6600; VA: 电容; FULL_LEAD_TIME: 49; ORDER_SEQ: 6; PPL_FLAG: 2; DFM: X; Life_Cycle_Flag: 4; Item_Priority: B; AP: Y; CompType: 刚玻/秖玻
J13 = GE_RJ45_2: VA: 网口插件
L78 = INDUCTOR_Dup1: VA: 电感
L79-L81 = INDUCTOR_Dup1: VA: 磁珠
R1098-R1105 R1108-R1115 = RESISTOR: VA: 电阻
R1106 R1107 = RESISTOR
RN23 = RESARR_IS_4/SM: VA: 排阻
U13 = JL2121D-N040I_0: VA: 芯片
Y12 = X3_0: VA: 无源晶振

## Sheet PAGE10 PL Ethernet4.SchDoc
size 386 x 279 mm
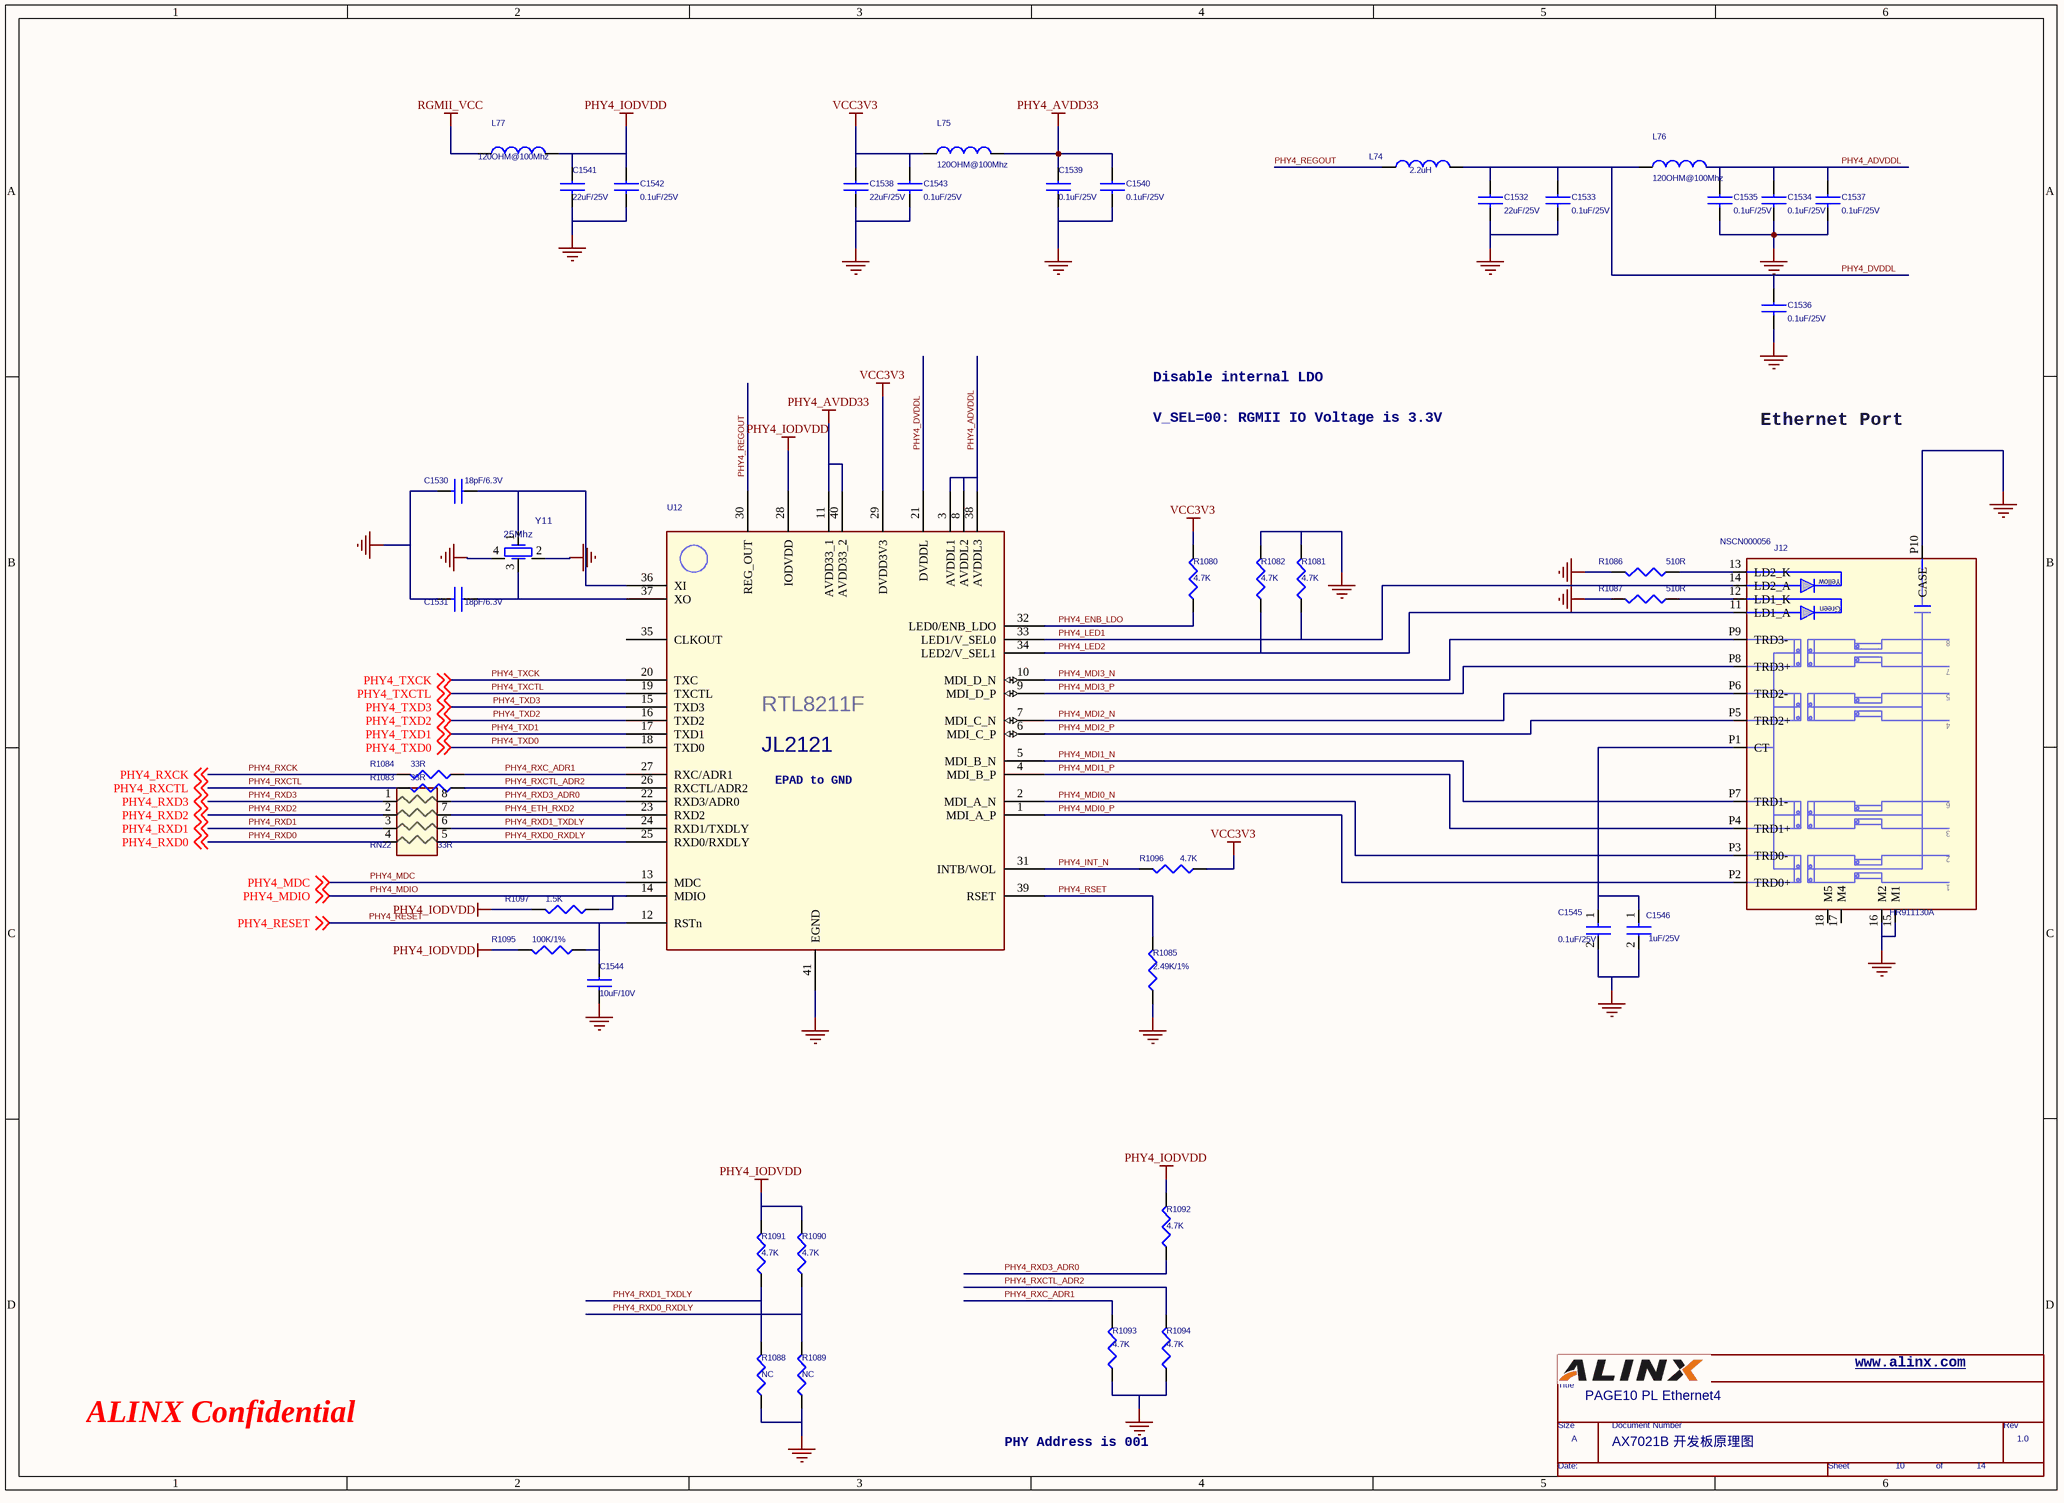
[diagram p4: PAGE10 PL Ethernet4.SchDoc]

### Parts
(Parts that share a designator on the sheet are numbered #1, #2 ... from top to bottom, then left to right.)
*#5  Doc: AX7021B 开发板原理图  RevCode: 1.0  Title: PAGE10 PL Ethernet4  Page Size: A  Page Number: 10  Page Count: 14  (hidden comment: TitleBlock0)  (graphical)
C1530  18pF/6.3V  [C0402]
C1531  18pF/6.3V  [C0402]
C1532  22uF/25V  [C0805]
C1533  0.1uF/25V  [C0402]
C1534  0.1uF/25V  [C0402]
C1535  0.1uF/25V  [C0402]
C1536  0.1uF/25V  [C0402]
C1537  0.1uF/25V  [C0402]
C1538  22uF/25V  [C0805]
C1539  0.1uF/25V  [C0402]
C1540  0.1uF/25V  [C0402]
C1541  22uF/25V  [C0805]
C1542  0.1uF/25V  [C0402]
C1543  0.1uF/25V  [C0402]
C1544  10uF/10V  [C0603]
C1545  0.1uF/25V  [C0402]
C1546  1uF/25V  [C0402]
J12  HR911130A  CODE: NSCN000056  [GE_RJ45]
L74  2.2uH  [LVS303010]
L75  120OHM@100Mhz  [L0603]
L76  120OHM@100Mhz  [L0603]
L77  120OHM@100Mhz  [L0603]
R1080  4.7K  [R0402]
R1081  4.7K  [R0402]
R1082  4.7K  [R0402]
R1083  33R  [R0402]
R1084  33R  [R0402]
R1085  2.49K/1%  [R0402]
R1086  510R  [R0402]
R1087  510R  [R0402]
R1088  NC  [R0402]
R1089  NC  [R0402]
R1090  4.7K  [R0402]
R1091  4.7K  [R0402]
R1092  4.7K  [R0402]
R1093  4.7K  [R0402]
R1094  4.7K  [R0402]
R1095  100K/1%  [R0402]
R1096  4.7K  [R0402]
R1097  1.5K  [R0402]
RN22  33R  [RN-8P]
U12  JL2121-N040I  [QFN40]  (value not drawn)
Y11  25Mhz  [OSC3225]

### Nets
GND: C1530.2 C1531.2 C1532.2 C1533.2 C1534.2 C1535.2 C1536.2 C1537.2 C1538.2 C1539.2 C1540.2 C1541.2 C1542.2 C1543.2 C1544.2 C1545.2 C1546.2 J12.15(M1) J12.16(M2) J12.P10(CASE) R1081.2 R1082.2 R1085.1 R1086.2 R1087.2 R1088.1 R1089.1 R1093.1 R1094.1 U12.41(EGND) Y11.2 Y11.4
PHY4_AVDD33: C1539.1 C1540.1 L75.2 U12.11(AVDD33_1) U12.40(AVDD33_2)
PHY4_IODVDD: C1541.1 C1542.1 L77.2 R1090.2 R1091.2 R1092.2 R1095.2 R1097.2 U12.28(IODVDD)
RGMII_VCC: L77.1
VCC3V3: C1538.1 C1543.1 L75.1 R1080.2 R1096.1 U12.29(DVDD3V3)
PHY4_ADVDDL: C1534.1 C1535.1 C1537.1 L76.2 U12.3(AVDDL1) U12.8(AVDDL2) U12.38(AVDDL3)
PHY4_DVDDL: C1532.1 C1533.1 C1536.1 L74.2 L76.1 U12.21(DVDDL)
PHY4_ENB_LDO: R1080.1 U12.32(LED0/ENB_LDO)
PHY4_ETH_RXD2: RN22.7 U12.23(RXD2)
PHY4_INT_N: R1096.2 U12.31(INTB/WOL)
PHY4_LED1: J12.14(LD2_A) R1081.1 U12.33(LED1/V_SEL0)
PHY4_LED2: J12.11(LD1_A) R1082.1 U12.34(LED2/V_SEL1)
PHY4_MDC: U12.13(MDC) ; off-sheet PHY4_MDC
PHY4_MDI0_N: J12.P3(TRD0-) U12.2(MDI_A_N)
PHY4_MDI0_P: J12.P2(TRD0+) U12.1(MDI_A_P)
PHY4_MDI1_N: J12.P7(TRD1-) U12.5(MDI_B_N)
PHY4_MDI1_P: J12.P4(TRD1+) U12.4(MDI_B_P)
PHY4_MDI2_N: J12.P6(TRD2-) U12.7(MDI_C_N)
PHY4_MDI2_P: J12.P5(TRD2+) U12.6(MDI_C_P)
PHY4_MDI3_N: J12.P9(TRD3-) U12.10(MDI_D_N)
PHY4_MDI3_P: J12.P8(TRD3+) U12.9(MDI_D_P)
PHY4_MDIO: R1097.1 U12.14(MDIO) ; off-sheet PHY4_MDIO
PHY4_REGOUT: L74.1 U12.30(REG_OUT)
PHY4_RESET: C1544.1 R1095.1 U12.12(RSTn) ; off-sheet PHY4_RESET
PHY4_RSET: R1085.2 U12.39(RSET)
PHY4_RXC_ADR1: R1084.1 R1093.2 U12.27(RXC/ADR1)
PHY4_RXCK: R1084.2 ; off-sheet PHY4_RXCK
PHY4_RXCTL: R1083.2 ; off-sheet PHY4_RXCTL
PHY4_RXCTL_ADR2: R1083.1 R1094.2 U12.26(RXCTL/ADR2)
PHY4_RXD0: RN22.4 ; off-sheet PHY4_RXD0
PHY4_RXD0_RXDLY: R1089.2 R1090.1 RN22.5 U12.25(RXD0/RXDLY)
PHY4_RXD1: RN22.3 ; off-sheet PHY4_RXD1
PHY4_RXD1_TXDLY: R1088.2 R1091.1 RN22.6 U12.24(RXD1/TXDLY)
PHY4_RXD2: RN22.2 ; off-sheet PHY4_RXD2
PHY4_RXD3: RN22.1 ; off-sheet PHY4_RXD3
PHY4_RXD3_ADR0: R1092.1 RN22.8 U12.22(RXD3/ADR0)
PHY4_TXCK: U12.20(TXC) ; off-sheet PHY4_TXCK
PHY4_TXCTL: U12.19(TXCTL) ; off-sheet PHY4_TXCTL
PHY4_TXD0: U12.18(TXD0) ; off-sheet PHY4_TXD0
PHY4_TXD1: U12.17(TXD1) ; off-sheet PHY4_TXD1
PHY4_TXD2: U12.16(TXD2) ; off-sheet PHY4_TXD2
PHY4_TXD3: U12.15(TXD3) ; off-sheet PHY4_TXD3
NetC1530_1: C1530.1 U12.36(XI) Y11.1
NetC1531_1: C1531.1 U12.37(XO) Y11.3
NetC1545_1: C1545.1 C1546.1 J12.P1(CT)
NetJ12_12: J12.12(LD1_K) R1087.1
NetJ12_13: J12.13(LD2_K) R1086.1

Not connected (* = marked no-connect by the designer): J12 17(M4) 18(M5); U12 35(CLKOUT)

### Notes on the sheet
- Disable internal LDO
- V_SEL=00: RGMII IO Voltage is 3.3V
- Ethernet Port
- www.alinx.com
- ALINX Confidential
- PHY Address is 001

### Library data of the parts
C1530-C1544 = CAP NP: VA: 电容
C1545 = CAP_3: MLCC,0402,GRM155R61A104KA01D(RoHS)(HF),0.1UF 10V X5R +-10%,MURATA; Part Number: 1A20-009R600; Manufacturer's Part Number: GRM155R61A104KA01D(GRM36X5R104K10)(RoHS); VA: 电容; CompType: 刚玻/秖玻; AP: Y; Item_Priority: B; Life_Cycle_Flag: 4; DFM: X; ORDER_SEQ: 6; FULL_LEAD_TIME: 42
C1546 = CAP_3: MLCC,0603,GRM188R61A105KA61D(RoHS),1UF 10V X5R +-10%,MURATA; Part Number: 1A30-00W6600; CompType: 刚玻/秖玻; AP: Y; Item_Priority: B; Life_Cycle_Flag: 4; DFM: X; PPL_FLAG: 2; ORDER_SEQ: 6; FULL_LEAD_TIME: 49; VA: 电容
J12 = GE_RJ45_2: VA: 网口插件
L74 = INDUCTOR_Dup1: VA: 电感
L75-L77 = INDUCTOR_Dup1: VA: 磁珠
R1080-R1087 R1090-R1097 = RESISTOR: VA: 电阻
R1088 R1089 = RESISTOR
RN22 = RESARR_IS_4/SM: VA: 排阻
U12 = JL2121D-N040I_0: VA: 芯片
Y11 = X3_0: VA: 无源晶振

## Sheet PAGE09 PL Ethernet3.SchDoc
size 386 x 279 mm
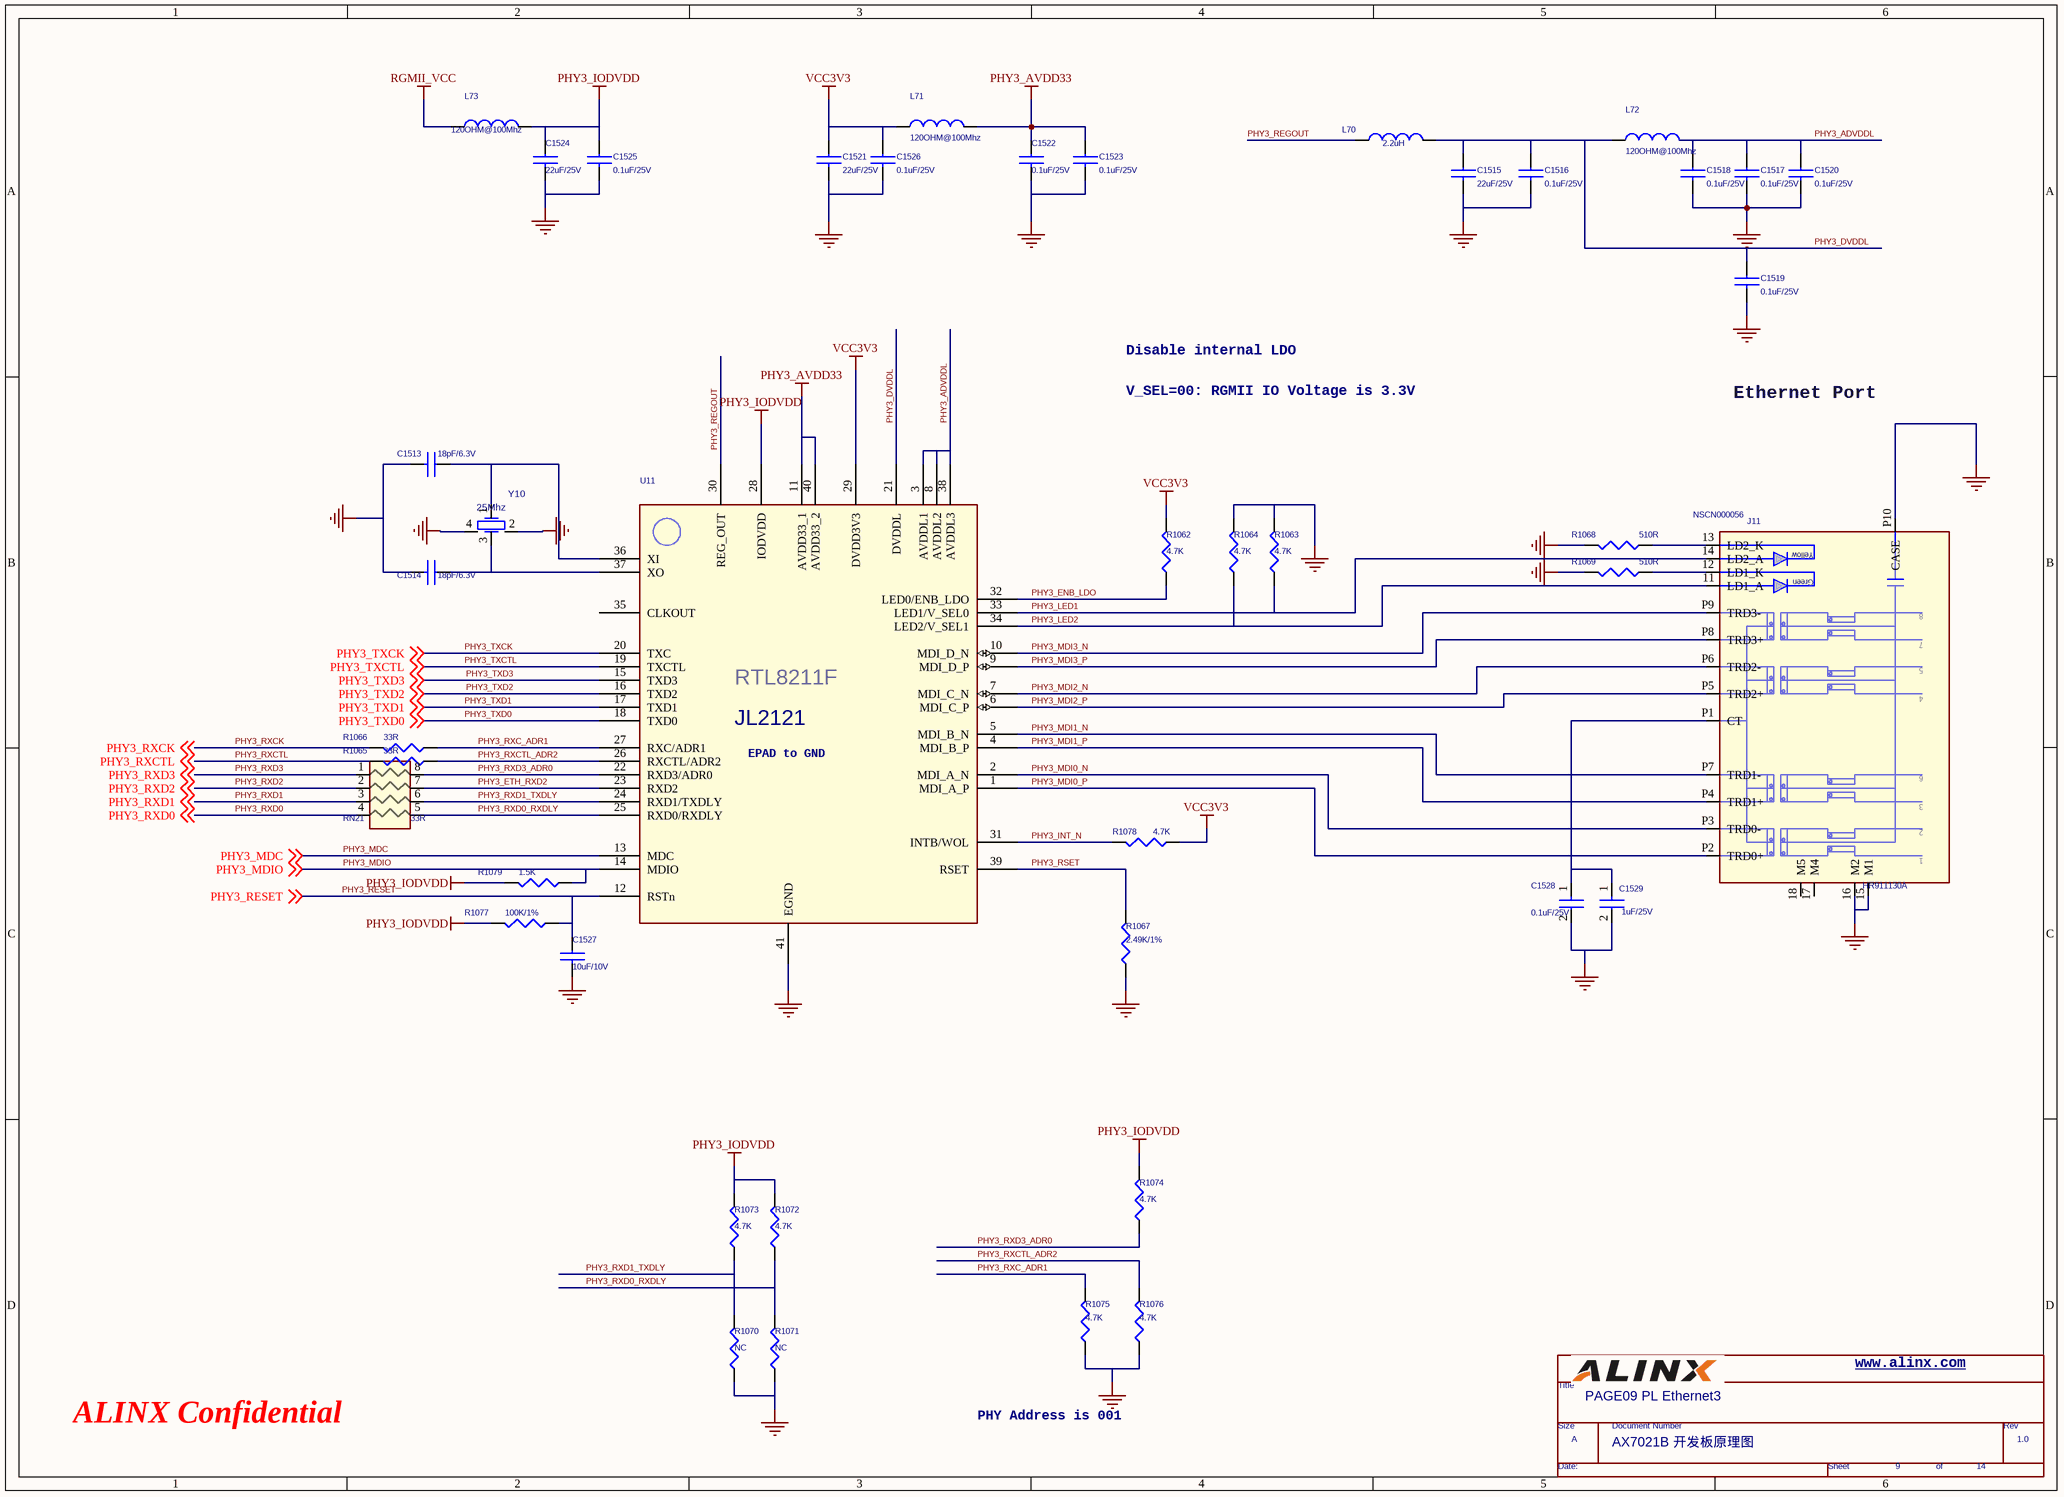
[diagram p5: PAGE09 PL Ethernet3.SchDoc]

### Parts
(Parts that share a designator on the sheet are numbered #1, #2 ... from top to bottom, then left to right.)
*#6  Doc: AX7021B 开发板原理图  RevCode: 1.0  Title: PAGE09 PL Ethernet3  Page Size: A  Page Number: 9  Page Count: 14  (hidden comment: TitleBlock0)  (graphical)
C1513  18pF/6.3V  [C0402]
C1514  18pF/6.3V  [C0402]
C1515  22uF/25V  [C0805]
C1516  0.1uF/25V  [C0402]
C1517  0.1uF/25V  [C0402]
C1518  0.1uF/25V  [C0402]
C1519  0.1uF/25V  [C0402]
C1520  0.1uF/25V  [C0402]
C1521  22uF/25V  [C0805]
C1522  0.1uF/25V  [C0402]
C1523  0.1uF/25V  [C0402]
C1524  22uF/25V  [C0805]
C1525  0.1uF/25V  [C0402]
C1526  0.1uF/25V  [C0402]
C1527  10uF/10V  [C0603]
C1528  0.1uF/25V  [C0402]
C1529  1uF/25V  [C0402]
J11  HR911130A  CODE: NSCN000056  [GE_RJ45]
L70  2.2uH  [LVS303010]
L71  120OHM@100Mhz  [L0603]
L72  120OHM@100Mhz  [L0603]
L73  120OHM@100Mhz  [L0603]
R1062  4.7K  [R0402]
R1063  4.7K  [R0402]
R1064  4.7K  [R0402]
R1065  33R  [R0402]
R1066  33R  [R0402]
R1067  2.49K/1%  [R0402]
R1068  510R  [R0402]
R1069  510R  [R0402]
R1070  NC  [R0402]
R1071  NC  [R0402]
R1072  4.7K  [R0402]
R1073  4.7K  [R0402]
R1074  4.7K  [R0402]
R1075  4.7K  [R0402]
R1076  4.7K  [R0402]
R1077  100K/1%  [R0402]
R1078  4.7K  [R0402]
R1079  1.5K  [R0402]
RN21  33R  [RN-8P]
U11  JL2121-N040I  [QFN40]  (value not drawn)
Y10  25Mhz  [OSC3225]

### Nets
GND: C1513.2 C1514.2 C1515.2 C1516.2 C1517.2 C1518.2 C1519.2 C1520.2 C1521.2 C1522.2 C1523.2 C1524.2 C1525.2 C1526.2 C1527.2 C1528.2 C1529.2 J11.15(M1) J11.16(M2) J11.P10(CASE) R1063.2 R1064.2 R1067.1 R1068.2 R1069.2 R1070.1 R1071.1 R1075.1 R1076.1 U11.41(EGND) Y10.2 Y10.4
PHY3_AVDD33: C1522.1 C1523.1 L71.2 U11.11(AVDD33_1) U11.40(AVDD33_2)
PHY3_IODVDD: C1524.1 C1525.1 L73.2 R1072.2 R1073.2 R1074.2 R1077.2 R1079.2 U11.28(IODVDD)
RGMII_VCC: L73.1
VCC3V3: C1521.1 C1526.1 L71.1 R1062.2 R1078.1 U11.29(DVDD3V3)
PHY3_ADVDDL: C1517.1 C1518.1 C1520.1 L72.2 U11.3(AVDDL1) U11.8(AVDDL2) U11.38(AVDDL3)
PHY3_DVDDL: C1515.1 C1516.1 C1519.1 L70.2 L72.1 U11.21(DVDDL)
PHY3_ENB_LDO: R1062.1 U11.32(LED0/ENB_LDO)
PHY3_ETH_RXD2: RN21.7 U11.23(RXD2)
PHY3_INT_N: R1078.2 U11.31(INTB/WOL)
PHY3_LED1: J11.14(LD2_A) R1063.1 U11.33(LED1/V_SEL0)
PHY3_LED2: J11.11(LD1_A) R1064.1 U11.34(LED2/V_SEL1)
PHY3_MDC: U11.13(MDC) ; off-sheet PHY3_MDC
PHY3_MDI0_N: J11.P3(TRD0-) U11.2(MDI_A_N)
PHY3_MDI0_P: J11.P2(TRD0+) U11.1(MDI_A_P)
PHY3_MDI1_N: J11.P7(TRD1-) U11.5(MDI_B_N)
PHY3_MDI1_P: J11.P4(TRD1+) U11.4(MDI_B_P)
PHY3_MDI2_N: J11.P6(TRD2-) U11.7(MDI_C_N)
PHY3_MDI2_P: J11.P5(TRD2+) U11.6(MDI_C_P)
PHY3_MDI3_N: J11.P9(TRD3-) U11.10(MDI_D_N)
PHY3_MDI3_P: J11.P8(TRD3+) U11.9(MDI_D_P)
PHY3_MDIO: R1079.1 U11.14(MDIO) ; off-sheet PHY3_MDIO
PHY3_REGOUT: L70.1 U11.30(REG_OUT)
PHY3_RESET: C1527.1 R1077.1 U11.12(RSTn) ; off-sheet PHY3_RESET
PHY3_RSET: R1067.2 U11.39(RSET)
PHY3_RXC_ADR1: R1066.1 R1075.2 U11.27(RXC/ADR1)
PHY3_RXCK: R1066.2 ; off-sheet PHY3_RXCK
PHY3_RXCTL: R1065.2 ; off-sheet PHY3_RXCTL
PHY3_RXCTL_ADR2: R1065.1 R1076.2 U11.26(RXCTL/ADR2)
PHY3_RXD0: RN21.4 ; off-sheet PHY3_RXD0
PHY3_RXD0_RXDLY: R1071.2 R1072.1 RN21.5 U11.25(RXD0/RXDLY)
PHY3_RXD1: RN21.3 ; off-sheet PHY3_RXD1
PHY3_RXD1_TXDLY: R1070.2 R1073.1 RN21.6 U11.24(RXD1/TXDLY)
PHY3_RXD2: RN21.2 ; off-sheet PHY3_RXD2
PHY3_RXD3: RN21.1 ; off-sheet PHY3_RXD3
PHY3_RXD3_ADR0: R1074.1 RN21.8 U11.22(RXD3/ADR0)
PHY3_TXCK: U11.20(TXC) ; off-sheet PHY3_TXCK
PHY3_TXCTL: U11.19(TXCTL) ; off-sheet PHY3_TXCTL
PHY3_TXD0: U11.18(TXD0) ; off-sheet PHY3_TXD0
PHY3_TXD1: U11.17(TXD1) ; off-sheet PHY3_TXD1
PHY3_TXD2: U11.16(TXD2) ; off-sheet PHY3_TXD2
PHY3_TXD3: U11.15(TXD3) ; off-sheet PHY3_TXD3
NetC1513_1: C1513.1 U11.36(XI) Y10.1
NetC1514_1: C1514.1 U11.37(XO) Y10.3
NetC1528_1: C1528.1 C1529.1 J11.P1(CT)
NetJ11_12: J11.12(LD1_K) R1069.1
NetJ11_13: J11.13(LD2_K) R1068.1

Not connected (* = marked no-connect by the designer): J11 17(M4) 18(M5); U11 35(CLKOUT)

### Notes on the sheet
- Disable internal LDO
- V_SEL=00: RGMII IO Voltage is 3.3V
- Ethernet Port
- www.alinx.com
- ALINX Confidential
- PHY Address is 001

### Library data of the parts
C1513-C1527 = CAP NP: VA: 电容
C1528 = CAP_3: as C1562 on sheet PAGE11 PL Ethernet5
C1529 = CAP_3: as C1563 on sheet PAGE11 PL Ethernet5
J11 = GE_RJ45_2: VA: 网口插件
L70 = INDUCTOR_Dup1: VA: 电感
L71-L73 = INDUCTOR_Dup1: VA: 磁珠
R1062-R1069 R1072-R1079 = RESISTOR: VA: 电阻
R1070 R1071 = RESISTOR
RN21 = RESARR_IS_4/SM: VA: 排阻
U11 = JL2121D-N040I_0: VA: 芯片
Y10 = X3_0: VA: 无源晶振

## Sheet PAGE08 PL Ethernet2.SchDoc
size 386 x 279 mm
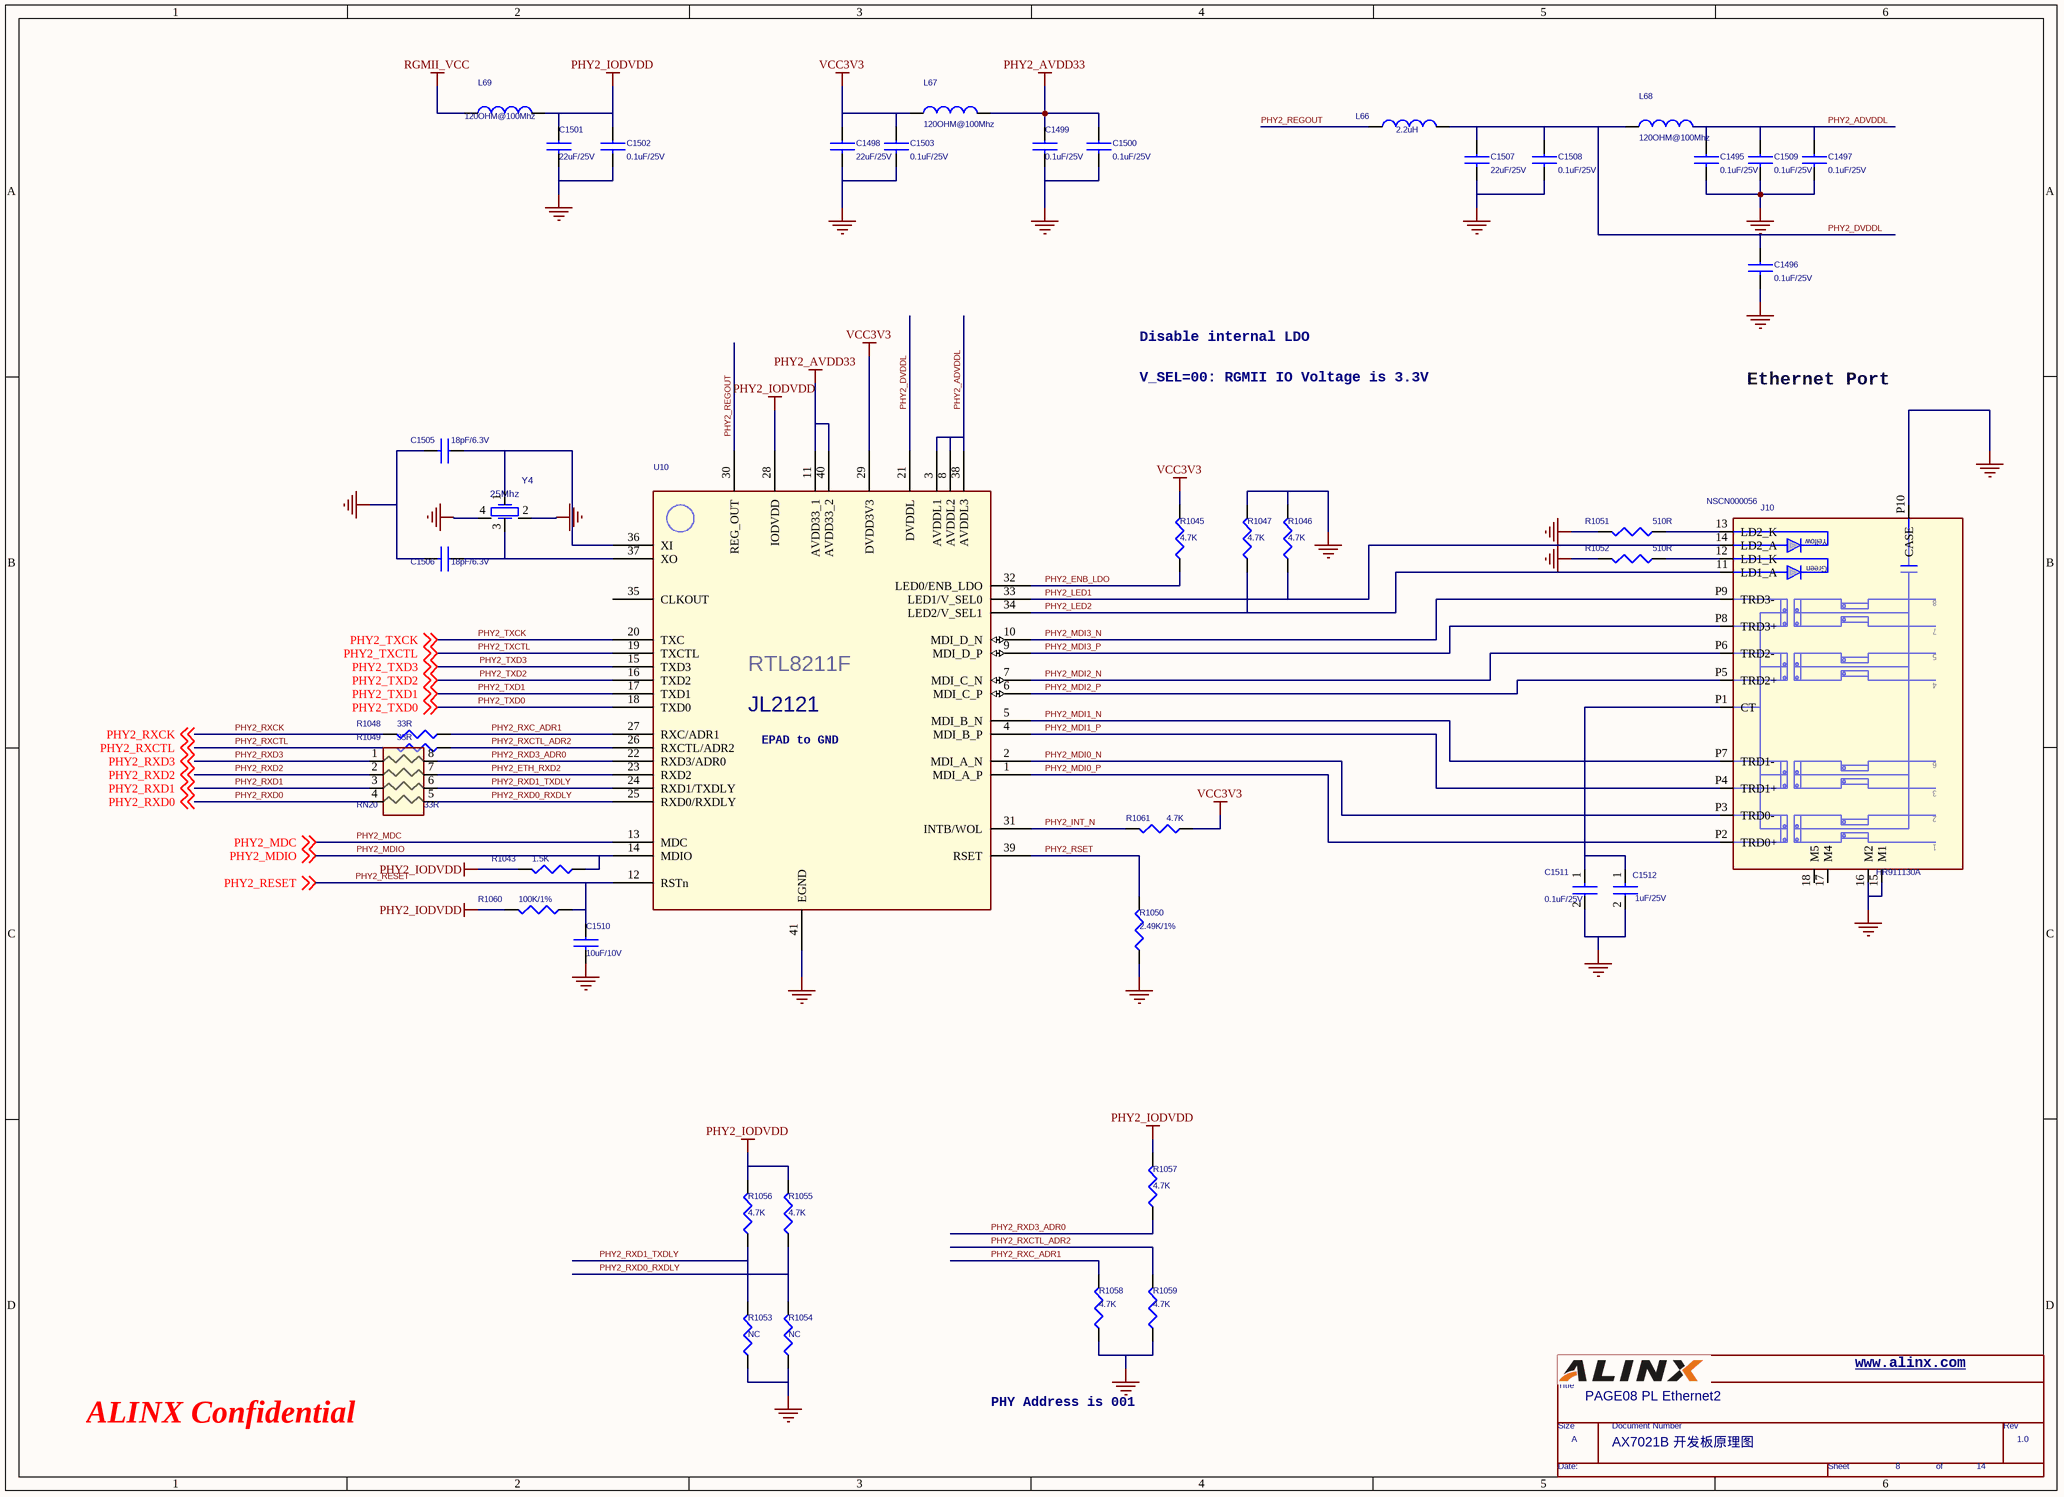
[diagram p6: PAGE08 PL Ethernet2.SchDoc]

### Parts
(Parts that share a designator on the sheet are numbered #1, #2 ... from top to bottom, then left to right.)
*#7  Doc: AX7021B 开发板原理图  RevCode: 1.0  Title: PAGE08 PL Ethernet2  Page Size: A  Page Number: 8  Page Count: 14  (hidden comment: TitleBlock0)  (graphical)
C1495  0.1uF/25V  [C0402]
C1496  0.1uF/25V  [C0402]
C1497  0.1uF/25V  [C0402]
C1498  22uF/25V  [C0805]
C1499  0.1uF/25V  [C0402]
C1500  0.1uF/25V  [C0402]
C1501  22uF/25V  [C0805]
C1502  0.1uF/25V  [C0402]
C1503  0.1uF/25V  [C0402]
C1505  18pF/6.3V  [C0402]
C1506  18pF/6.3V  [C0402]
C1507  22uF/25V  [C0805]
C1508  0.1uF/25V  [C0402]
C1509  0.1uF/25V  [C0402]
C1510  10uF/10V  [C0603]
C1511  0.1uF/25V  [C0402]
C1512  1uF/25V  [C0402]
J10  HR911130A  CODE: NSCN000056  [GE_RJ45]
L66  2.2uH  [LVS303010]
L67  120OHM@100Mhz  [L0603]
L68  120OHM@100Mhz  [L0603]
L69  120OHM@100Mhz  [L0603]
R1043  1.5K  [R0402]
R1045  4.7K  [R0402]
R1046  4.7K  [R0402]
R1047  4.7K  [R0402]
R1048  33R  [R0402]
R1049  33R  [R0402]
R1050  2.49K/1%  [R0402]
R1051  510R  [R0402]
R1052  510R  [R0402]
R1053  NC  [R0402]
R1054  NC  [R0402]
R1055  4.7K  [R0402]
R1056  4.7K  [R0402]
R1057  4.7K  [R0402]
R1058  4.7K  [R0402]
R1059  4.7K  [R0402]
R1060  100K/1%  [R0402]
R1061  4.7K  [R0402]
RN20  33R  [RN-8P]
U10  JL2121-N040I  [QFN40]  (value not drawn)
Y4  25Mhz  [OSC3225]

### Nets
GND: C1495.2 C1496.2 C1497.2 C1498.2 C1499.2 C1500.2 C1501.2 C1502.2 C1503.2 C1505.2 C1506.2 C1507.2 C1508.2 C1509.2 C1510.2 C1511.2 C1512.2 J10.15(M1) J10.16(M2) J10.P10(CASE) R1046.2 R1047.2 R1050.1 R1051.2 R1052.2 R1053.1 R1054.1 R1058.1 R1059.1 U10.41(EGND) Y4.2 Y4.4
PHY2_AVDD33: C1499.1 C1500.1 L67.2 U10.11(AVDD33_1) U10.40(AVDD33_2)
PHY2_IODVDD: C1501.1 C1502.1 L69.2 R1043.2 R1055.2 R1056.2 R1057.2 R1060.2 U10.28(IODVDD)
RGMII_VCC: L69.1
VCC3V3: C1498.1 C1503.1 L67.1 R1045.2 R1061.1 U10.29(DVDD3V3)
PHY2_ADVDDL: C1495.1 C1497.1 C1509.1 L68.2 U10.3(AVDDL1) U10.8(AVDDL2) U10.38(AVDDL3)
PHY2_DVDDL: C1496.1 C1507.1 C1508.1 L66.2 L68.1 U10.21(DVDDL)
PHY2_ENB_LDO: R1045.1 U10.32(LED0/ENB_LDO)
PHY2_ETH_RXD2: RN20.7 U10.23(RXD2)
PHY2_INT_N: R1061.2 U10.31(INTB/WOL)
PHY2_LED1: J10.14(LD2_A) R1046.1 U10.33(LED1/V_SEL0)
PHY2_LED2: J10.11(LD1_A) R1047.1 U10.34(LED2/V_SEL1)
PHY2_MDC: U10.13(MDC) ; off-sheet PHY2_MDC
PHY2_MDI0_N: J10.P3(TRD0-) U10.2(MDI_A_N)
PHY2_MDI0_P: J10.P2(TRD0+) U10.1(MDI_A_P)
PHY2_MDI1_N: J10.P7(TRD1-) U10.5(MDI_B_N)
PHY2_MDI1_P: J10.P4(TRD1+) U10.4(MDI_B_P)
PHY2_MDI2_N: J10.P6(TRD2-) U10.7(MDI_C_N)
PHY2_MDI2_P: J10.P5(TRD2+) U10.6(MDI_C_P)
PHY2_MDI3_N: J10.P9(TRD3-) U10.10(MDI_D_N)
PHY2_MDI3_P: J10.P8(TRD3+) U10.9(MDI_D_P)
PHY2_MDIO: R1043.1 U10.14(MDIO) ; off-sheet PHY2_MDIO
PHY2_REGOUT: L66.1 U10.30(REG_OUT)
PHY2_RESET: C1510.1 R1060.1 U10.12(RSTn) ; off-sheet PHY2_RESET
PHY2_RSET: R1050.2 U10.39(RSET)
PHY2_RXC_ADR1: R1048.1 R1058.2 U10.27(RXC/ADR1)
PHY2_RXCK: R1048.2 ; off-sheet PHY2_RXCK
PHY2_RXCTL: R1049.2 ; off-sheet PHY2_RXCTL
PHY2_RXCTL_ADR2: R1049.1 R1059.2 U10.26(RXCTL/ADR2)
PHY2_RXD0: RN20.4 ; off-sheet PHY2_RXD0
PHY2_RXD0_RXDLY: R1054.2 R1055.1 RN20.5 U10.25(RXD0/RXDLY)
PHY2_RXD1: RN20.3 ; off-sheet PHY2_RXD1
PHY2_RXD1_TXDLY: R1053.2 R1056.1 RN20.6 U10.24(RXD1/TXDLY)
PHY2_RXD2: RN20.2 ; off-sheet PHY2_RXD2
PHY2_RXD3: RN20.1 ; off-sheet PHY2_RXD3
PHY2_RXD3_ADR0: R1057.1 RN20.8 U10.22(RXD3/ADR0)
PHY2_TXCK: U10.20(TXC) ; off-sheet PHY2_TXCK
PHY2_TXCTL: U10.19(TXCTL) ; off-sheet PHY2_TXCTL
PHY2_TXD0: U10.18(TXD0) ; off-sheet PHY2_TXD0
PHY2_TXD1: U10.17(TXD1) ; off-sheet PHY2_TXD1
PHY2_TXD2: U10.16(TXD2) ; off-sheet PHY2_TXD2
PHY2_TXD3: U10.15(TXD3) ; off-sheet PHY2_TXD3
NetC1505_1: C1505.1 U10.36(XI) Y4.1
NetC1506_1: C1506.1 U10.37(XO) Y4.3
NetC1511_1: C1511.1 C1512.1 J10.P1(CT)
NetJ10_12: J10.12(LD1_K) R1052.1
NetJ10_13: J10.13(LD2_K) R1051.1

Not connected (* = marked no-connect by the designer): J10 17(M4) 18(M5); U10 35(CLKOUT)

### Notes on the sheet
- Disable internal LDO
- V_SEL=00: RGMII IO Voltage is 3.3V
- Ethernet Port
- www.alinx.com
- ALINX Confidential
- PHY Address is 001

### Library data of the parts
C1495-C1503 C1505-C1510 = CAP NP: VA: 电容
C1511 = CAP_3: as C1562 on sheet PAGE11 PL Ethernet5
C1512 = CAP_3: as C1563 on sheet PAGE11 PL Ethernet5
J10 = GE_RJ45_2: VA: 网口插件
L66 = INDUCTOR_Dup1: VA: 电感
L67-L69 = INDUCTOR_Dup1: VA: 磁珠
R1043 R1045-R1052 R1055-R1061 = RESISTOR: VA: 电阻
R1053 R1054 = RESISTOR
RN20 = RESARR_IS_4/SM: VA: 排阻
U10 = JL2121D-N040I_0: VA: 芯片
Y4 = X3_0: VA: 无源晶振

## Sheet PAGE07 HDMI OUT.SchDoc
size 386 x 279 mm
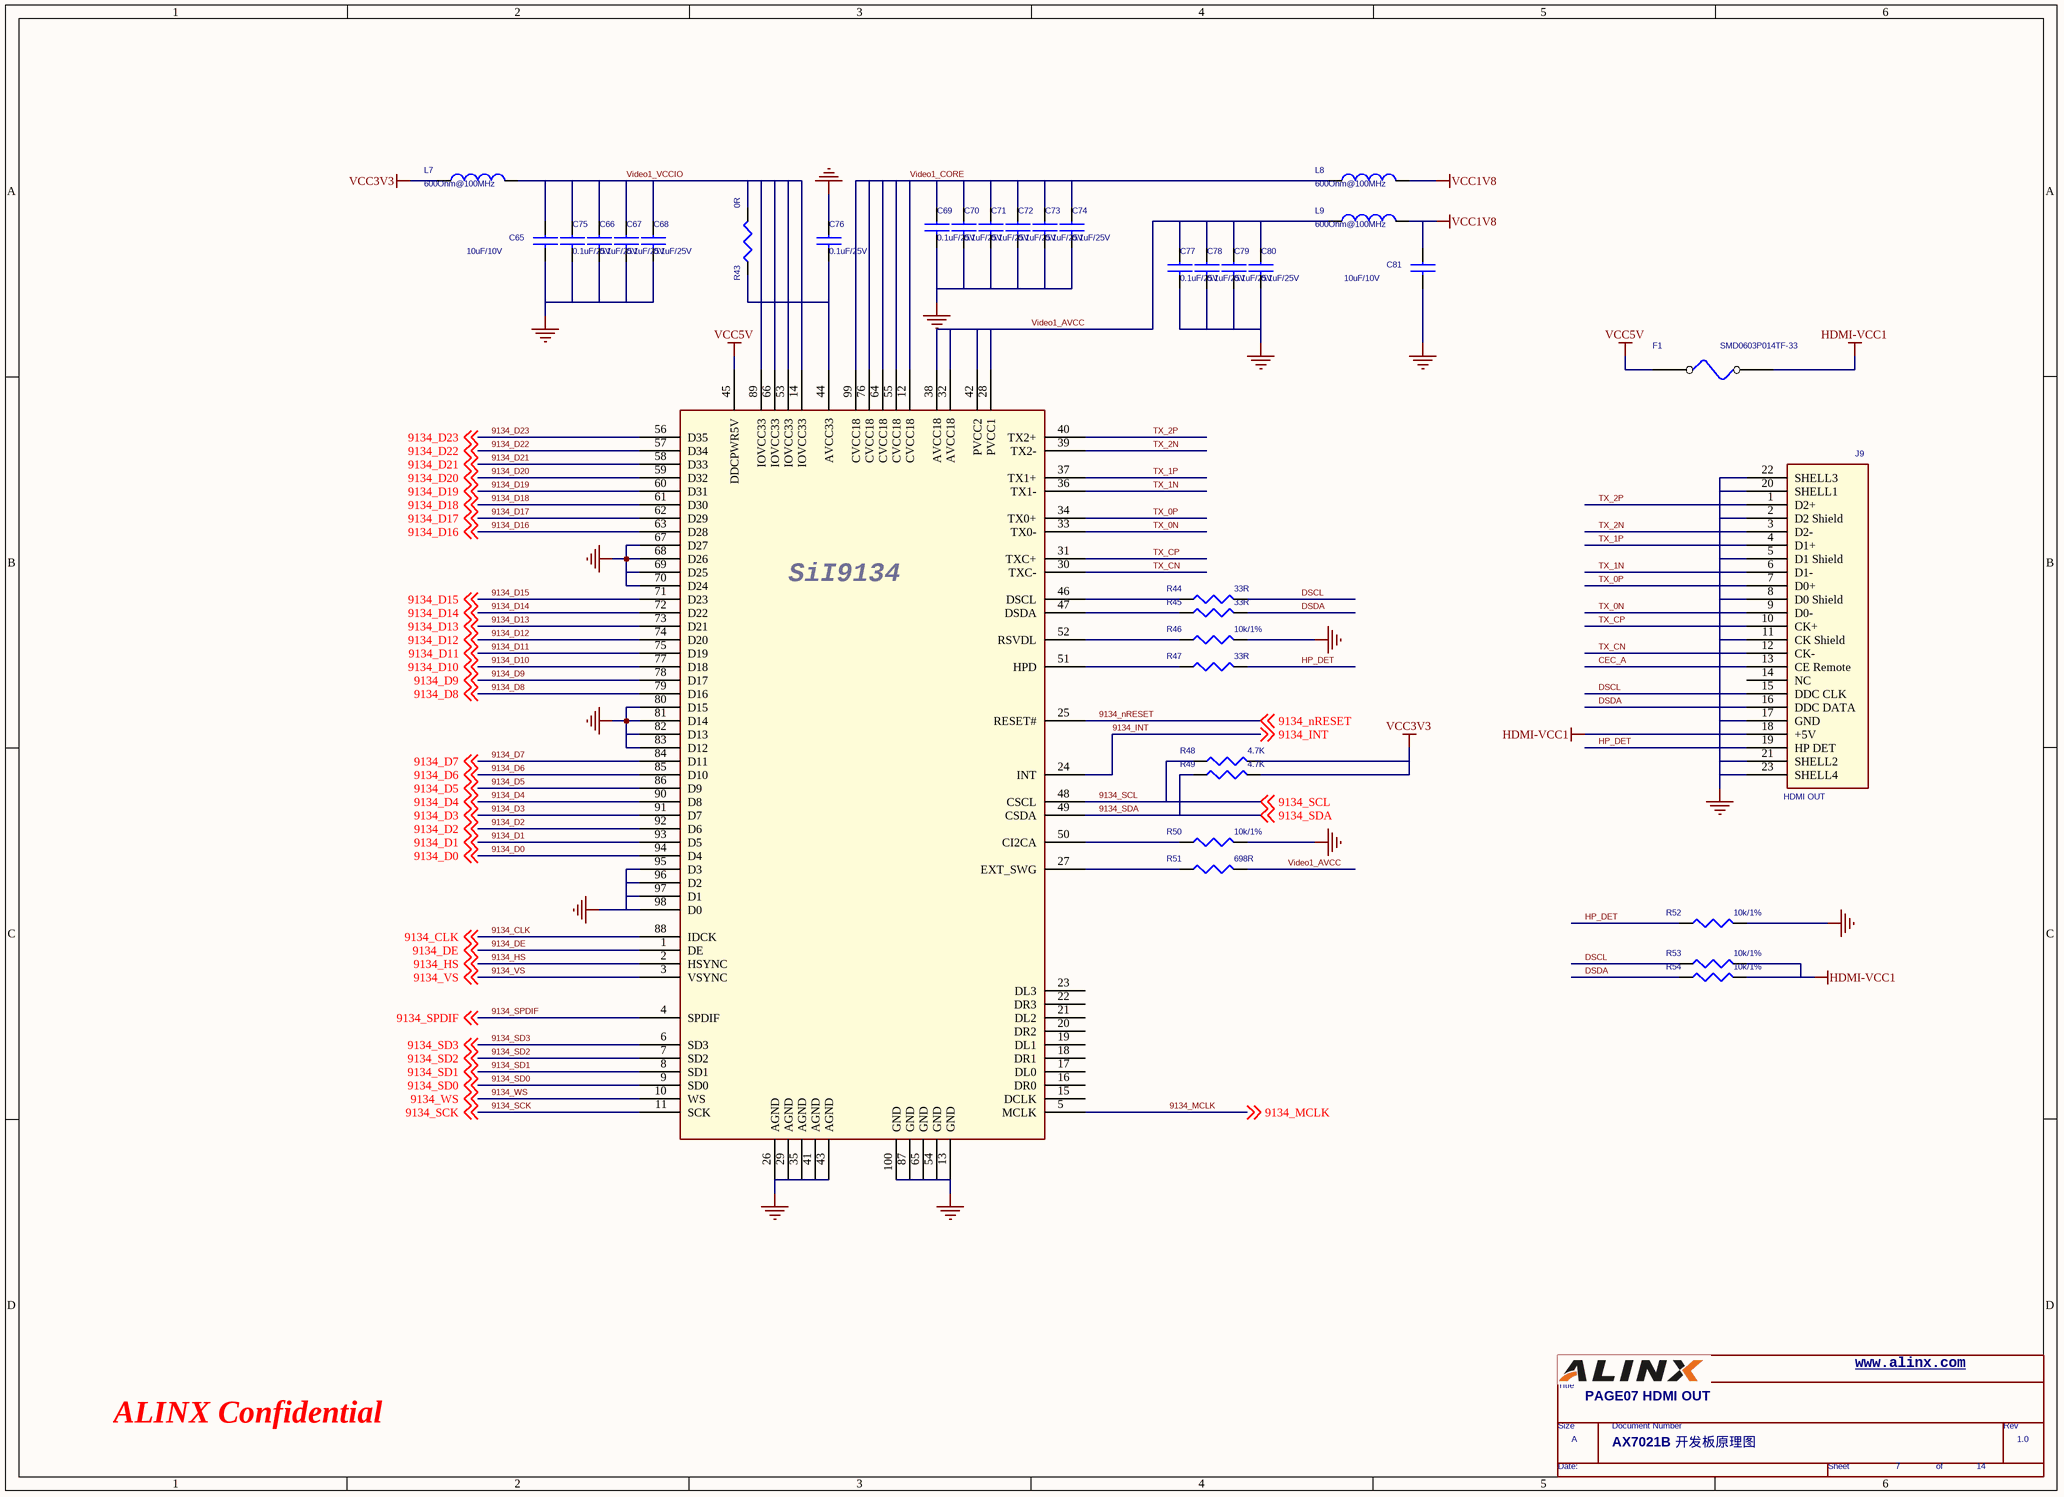
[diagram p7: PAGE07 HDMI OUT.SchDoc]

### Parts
(Parts that share a designator on the sheet are numbered #1, #2 ... from top to bottom, then left to right.)
*#8  Doc: AX7021B 开发板原理图  RevCode: 1.0  Title: PAGE07 HDMI OUT  Page Size: A  Page Number: 7  Page Count: 14  (hidden comment: TitleBlock0)  (graphical)
C65  10uF/10V  [C0603]
C66  0.1uF/25V  [C0402]
C67  0.1uF/25V  [C0402]
C68  0.1uF/25V  [C0402]
C69  0.1uF/25V  [C0402]
C70  0.1uF/25V  [C0402]
C71  0.1uF/25V  [C0402]
C72  0.1uF/25V  [C0402]
C73  0.1uF/25V  [C0402]
C74  0.1uF/25V  [C0402]
C75  0.1uF/25V  [C0402]
C76  0.1uF/25V  [C0402]
C77  0.1uF/25V  [C0402]
C78  0.1uF/25V  [C0402]
C79  0.1uF/25V  [C0402]
C80  0.1uF/25V  [C0402]
C81  10uF/10V  [C0603]
F1  SMD0603P014TF-33  [L0603]
J9  HDMI OUT  [SMT]
L7  600Ohm@100MHz  [L0603]
L8  600Ohm@100MHz  [L0603]
L9  600Ohm@100MHz  [L0603]
R43  0R  [R0603]
R44  33R  [R0402]
R45  33R  [R0402]
R46  10k/1%  [R0402]
R47  33R  [R0402]
R48  4.7K  [R0402]
R49  4.7K  [R0402]
R50  10k/1%  [R0402]
R51  698R  [R0402]
R52  10k/1%  [R0402]
R53  10k/1%  [R0402]
R54  10k/1%  [R0402]
U9  SiI9134  [QFP-100]  (value not drawn)

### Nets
GND: C65.2 C66.2 C67.2 C68.2 C69.2 C70.2 C71.2 C72.2 C73.2 C74.2 C75.2 C76.1 C77.2 C78.2 C79.2 C80.2 C81.2 J9.2(D2_Shield) J9.5(D1_Shield) J9.8(D0_Shield) J9.11(CK_Shield) J9.17(GND) J9.20(SHELL1) J9.21(SHELL2) J9.22(SHELL3) J9.23(SHELL4) R46.2 R50.2 R52.2 U9.13(GND) U9.26(AGND) U9.29(AGND) U9.35(AGND) U9.41(AGND) U9.43(AGND) U9.54(GND) U9.65(GND) U9.67(D27) U9.68(D26) U9.69(D25) U9.70(D24) U9.80(D15) U9.81(D14) U9.82(D13) U9.83(D12) U9.87(GND) U9.95(D3) U9.96(D2) U9.97(D1) U9.98(D0) U9.100(GND)
HDMI-VCC1: F1.2 J9.18(+5V) R53.2 R54.2
VCC1V8: C81.1 L8.2 L9.2
VCC3V3: L7.1 R48.2 R49.2
VCC5V: F1.1 U9.45(DDCPWR5V)
9134_CLK: U9.88(IDCK) ; off-sheet 9134_CLK
9134_D0: U9.94(D4) ; off-sheet 9134_D0
9134_D1: U9.93(D5) ; off-sheet 9134_D1
9134_D2: U9.92(D6) ; off-sheet 9134_D2
9134_D3: U9.91(D7) ; off-sheet 9134_D3
9134_D4: U9.90(D8) ; off-sheet 9134_D4
9134_D5: U9.86(D9) ; off-sheet 9134_D5
9134_D6: U9.85(D10) ; off-sheet 9134_D6
9134_D7: U9.84(D11) ; off-sheet 9134_D7
9134_D8: U9.79(D16) ; off-sheet 9134_D8
9134_D9: U9.78(D17) ; off-sheet 9134_D9
9134_D10: U9.77(D18) ; off-sheet 9134_D10
9134_D11: U9.75(D19) ; off-sheet 9134_D11
9134_D12: U9.74(D20) ; off-sheet 9134_D12
9134_D13: U9.73(D21) ; off-sheet 9134_D13
9134_D14: U9.72(D22) ; off-sheet 9134_D14
9134_D15: U9.71(D23) ; off-sheet 9134_D15
9134_D16: U9.63(D28) ; off-sheet 9134_D16
9134_D17: U9.62(D29) ; off-sheet 9134_D17
9134_D18: U9.61(D30) ; off-sheet 9134_D18
9134_D19: U9.60(D31) ; off-sheet 9134_D19
9134_D20: U9.59(D32) ; off-sheet 9134_D20
9134_D21: U9.58(D33) ; off-sheet 9134_D21
9134_D22: U9.57(D34) ; off-sheet 9134_D22
9134_D23: U9.56(D35) ; off-sheet 9134_D23
9134_DE: U9.1(DE) ; off-sheet 9134_DE
9134_HS: U9.2(HSYNC) ; off-sheet 9134_HS
9134_INT: U9.24(INT) ; off-sheet 9134_INT
9134_MCLK: U9.5(MCLK) ; off-sheet 9134_MCLK
9134_nRESET: U9.25(RESET#) ; off-sheet 9134_nRESET
9134_SCK: U9.11(SCK) ; off-sheet 9134_SCK
9134_SCL: R48.1 U9.48(CSCL) ; off-sheet 9134_SCL
9134_SD0: U9.9(SD0) ; off-sheet 9134_SD0
9134_SD1: U9.8(SD1) ; off-sheet 9134_SD1
9134_SD2: U9.7(SD2) ; off-sheet 9134_SD2
9134_SD3: U9.6(SD3) ; off-sheet 9134_SD3
9134_SDA: R49.1 U9.49(CSDA) ; off-sheet 9134_SDA
9134_SPDIF: U9.4(SPDIF) ; off-sheet 9134_SPDIF
9134_VS: U9.3(VSYNC) ; off-sheet 9134_VS
9134_WS: U9.10(WS) ; off-sheet 9134_WS
CEC_A: J9.13(CE_Remote)
DSCL: J9.15(DDC_CLK) R44.2 R53.1
DSDA: J9.16(DDC_DATA) R45.2 R54.1
HP_DET: J9.19(HP_DET) R47.2 R52.1
TX_0N: J9.9(D0-) U9.33(TX0-)
TX_0P: J9.7(D0+) U9.34(TX0+)
TX_1N: J9.6(D1-) U9.36(TX1-)
TX_1P: J9.4(D1+) U9.37(TX1+)
TX_2N: J9.3(D2-) U9.39(TX2-)
TX_2P: J9.1(D2+) U9.40(TX2+)
TX_CN: J9.12(CK-) U9.30(TXC-)
TX_CP: J9.10(CK+) U9.31(TXC+)
Video1_AVCC: C77.1 C78.1 C79.1 C80.1 L9.1 R51.2 U9.28(PVCC1) U9.32(AVCC18) U9.38(AVCC18) U9.42(PVCC2)
Video1_CORE: C69.1 C70.1 C71.1 C72.1 C73.1 C74.1 L8.1 U9.12(CVCC18) U9.55(CVCC18) U9.64(CVCC18) U9.76(CVCC18) U9.99(CVCC18)
Video1_VCCIO: C65.1 C66.1 C67.1 C68.1 C75.1 L7.2 R43.2 U9.14(IOVCC33) U9.53(IOVCC33) U9.66(IOVCC33) U9.89(IOVCC33)
NetC76_2: C76.2 R43.1 U9.44(AVCC33)
NetR44_1: R44.1 U9.46(DSCL)
NetR45_1: R45.1 U9.47(DSDA)
NetR46_1: R46.1 U9.52(RSVDL)
NetR47_1: R47.1 U9.51(HPD)
NetR50_1: R50.1 U9.50(CI2CA)
NetR51_1: R51.1 U9.27(EXT_SWG)

Not connected (* = marked no-connect by the designer): J9 14(NC); U9 15(DCLK) 16(DR0) 17(DL0) 18(DR1) 19(DL1) 20(DR2) 21(DL2) 22(DR3) 23(DL3)

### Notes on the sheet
- www.alinx.com
- ALINX Confidential

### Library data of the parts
C65 C81 = CAP NP: VA: 电容
C66-C80 = C_1: PART NUMBER: 1802-00187D; VA: 电容
F1 = FUSE/SM: VA: 自恢复保险丝
J9 = HDMI Connector_0: HDMI connector; 04 MPN: SD-500254-001; Vendor P/N: xxxx-xxxx; MFG: JAE xxxx-xxx; Vendor: JAE; 02 DESC: CONN, HDMI connector R/A; 03 MAN: MOLEX; VA: HDMI接口
L7-L9 = INDUCTOR: VA: 磁珠
R43-R54 = R_0: VA: 电阻
U9 = SiI9134_0: VA: 芯片

## Sheet PAGE06 HOST USB X 4.SchDoc
size 386 x 279 mm
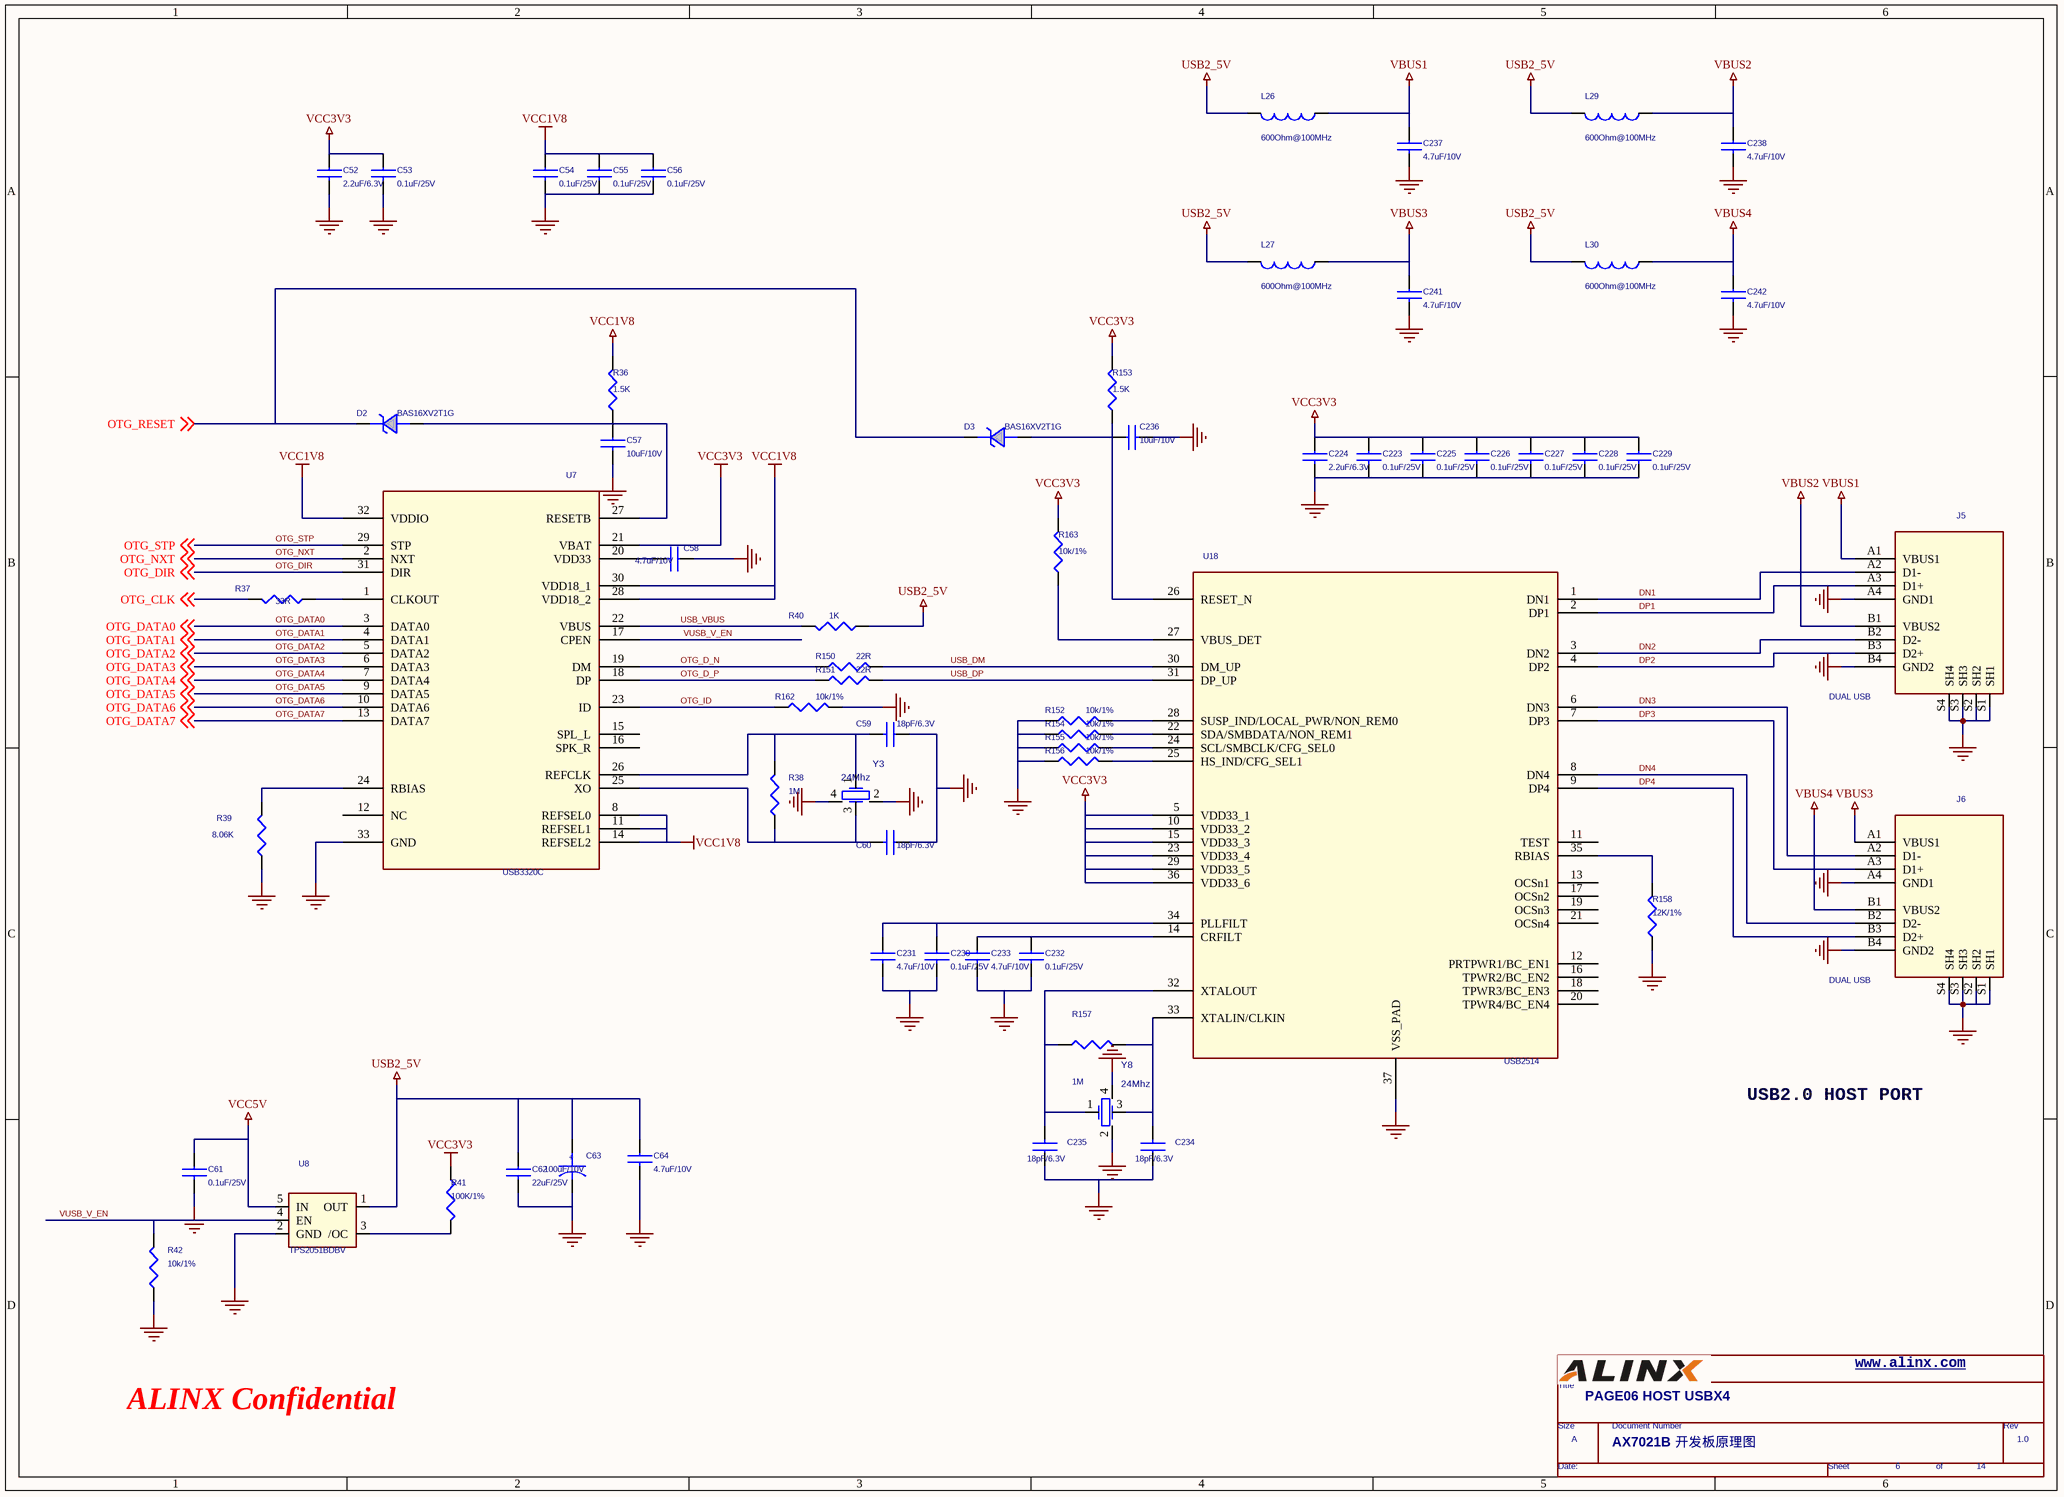
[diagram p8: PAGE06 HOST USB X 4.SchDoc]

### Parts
(Parts that share a designator on the sheet are numbered #1, #2 ... from top to bottom, then left to right.)
*#9  Doc: AX7021B 开发板原理图  RevCode: 1.0  Title: PAGE06 HOST USBX4  Page Size: A  Page Number: 6  Page Count: 14  (hidden comment: TitleBlock0)  (graphical)
C52  2.2uF/6.3V  [C0402]
C53  0.1uF/25V  [C0402]
C54  0.1uF/25V  [C0402]
C55  0.1uF/25V  [C0402]
C56  0.1uF/25V  [C0402]
C57  10uF/10V  [C0603]
C58  4.7uF/10V  [C0402]
C59  18pF/6.3V  [C0402]
C60  18pF/6.3V  [C0402]
C61  0.1uF/25V  [C0402]
C62  22uF/25V  [C0805]
C63  100uF/10V  [TAN-SMB]
C64  4.7uF/10V  [C0402]
C223  0.1uF/25V  [C0402]
C224  2.2uF/6.3V  [C0402]
C225  0.1uF/25V  [C0402]
C226  0.1uF/25V  [C0402]
C227  0.1uF/25V  [C0402]
C228  0.1uF/25V  [C0402]
C229  0.1uF/25V  [C0402]
C230  0.1uF/25V  [C0402]
C231  4.7uF/10V  [C0402]
C232  0.1uF/25V  [C0402]
C233  4.7uF/10V  [C0402]
C234  18pF/6.3V  [C0402]
C235  18pF/6.3V  [C0402]
C236  10uF/10V  [C0603]
C237  4.7uF/10V  [C0402]
C238  4.7uF/10V  [C0402]
C241  4.7uF/10V  [C0402]
C242  4.7uF/10V  [C0402]
D2  BAS16XV2T1G  [SOD-523]
D3  BAS16XV2T1G  [SOD-523]
J5  DUAL USB  [DUAL_USB]
J6  DUAL USB  [DUAL_USB]
L26  600Ohm@100MHz  [L0603]
L27  600Ohm@100MHz  [L0603]
L29  600Ohm@100MHz  [L0603]
L30  600Ohm@100MHz  [L0603]
R36  1.5K  [R0402]
R37  33R  [R0402]
R38  1M  [R0402]
R39  8.06K  [R0402]
R40  1K  [R0402]
R41  100K/1%  [R0402]
R42  10k/1%  [R0402]
R150  22R  [R0402]
R151  22R  [R0402]
R152  10k/1%  [R0402]
R153  1.5K  [R0402]
R154  10k/1%  [R0402]
R155  10k/1%  [R0402]
R156  10k/1%  [R0402]
R157  1M  [R0402]
R158  12K/1%  [R0402]
R162  10k/1%  [R0402]
R163  10k/1%  [R0402]
U7  USB3320C  [USB3320C-EZK]
U8  TPS2051BDBV  [TPS2051BDBV]
U18  USB2514  [QFN-48]
Y3  24Mhz  [OSC3225]
Y8  24Mhz  [OSC3225]

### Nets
GND: C52.2 C53.2 C54.2 C55.2 C56.2 C57.2 C58.1 C59.1 C60.1 C61.2 C62.2 C63.2 C64.2 C223.2 C224.2 C225.2 C226.2 C227.2 C228.2 C229.2 C230.2 C231.2 C232.2 C233.2 C234.1 C235.1 C236.2 C237.2 C238.2 C241.2 C242.2 J5.A4(GND1) J5.B4(GND2) J5.S1(SH1) J5.S2(SH2) J5.S3(SH3) J5.S4(SH4) J6.A4(GND1) J6.B4(GND2) J6.S1(SH1) J6.S2(SH2) J6.S3(SH3) J6.S4(SH4) R39.1 R42.1 R152.1 R154.1 R155.1 R156.1 R158.1 R162.2 U7.33(GND) U8.2(GND) U18.37(VSS_PAD) Y3.2 Y3.4 Y8.2 Y8.4
USB2_5V: C62.1 C63.1 C64.1 L26.2 L27.2 L29.2 L30.2 R40.1 U8.1(OUT)
VBUS1: C237.1 J5.A1(VBUS1) L26.1
VBUS2: C238.1 J5.B1(VBUS2) L29.1
VBUS3: C241.1 J6.A1(VBUS1) L27.1
VBUS4: C242.1 J6.B1(VBUS2) L30.1
VCC1V8: C54.1 C55.1 C56.1 R36.2 U7.8(REFSEL0) U7.11(REFSEL1) U7.14(REFSEL2) U7.28(VDD18_2) U7.30(VDD18_1) U7.32(VDDIO)
VCC3V3: C52.1 C53.1 C223.1 C224.1 C225.1 C226.1 C227.1 C228.1 C229.1 R41.1 R153.2 R163.2 U7.21(VBAT) U18.5(VDD33_1) U18.10(VDD33_2) U18.15(VDD33_3) U18.23(VDD33_4) U18.29(VDD33_5) U18.36(VDD33_6)
VCC5V: C61.1 U8.5(IN)
DN1: J5.A2(D1-) U18.1(DN1)
DN2: J5.B2(D2-) U18.3(DN2)
DN3: J6.A2(D1-) U18.6(DN3)
DN4: J6.B2(D2-) U18.8(DN4)
DP1: J5.A3(D1+) U18.2(DP1)
DP2: J5.B3(D2+) U18.4(DP2)
DP3: J6.A3(D1+) U18.7(DP3)
DP4: J6.B3(D2+) U18.9(DP4)
OTG_CLK: R37.1 ; off-sheet OTG_CLK
OTG_D_N: R150.1 U7.19(DM)
OTG_D_P: R151.1 U7.18(DP)
OTG_DATA0: U7.3(DATA0) ; off-sheet OTG_DATA0
OTG_DATA1: U7.4(DATA1) ; off-sheet OTG_DATA1
OTG_DATA2: U7.5(DATA2) ; off-sheet OTG_DATA2
OTG_DATA3: U7.6(DATA3) ; off-sheet OTG_DATA3
OTG_DATA4: U7.7(DATA4) ; off-sheet OTG_DATA4
OTG_DATA5: U7.9(DATA5) ; off-sheet OTG_DATA5
OTG_DATA6: U7.10(DATA6) ; off-sheet OTG_DATA6
OTG_DATA7: U7.13(DATA7) ; off-sheet OTG_DATA7
OTG_DIR: U7.31(DIR) ; off-sheet OTG_DIR
OTG_ID: R162.1 U7.23(ID)
OTG_NXT: U7.2(NXT) ; off-sheet OTG_NXT
OTG_RESET: D2.1(CATHODE) D3.1(CATHODE) ; off-sheet OTG_RESET
OTG_STP: U7.29(STP) ; off-sheet OTG_STP
USB_DM: R150.2 U18.30(DM_UP)
USB_DP: R151.2 U18.31(DP_UP)
USB_VBUS: R40.2 U7.22(VBUS)
VUSB_V_EN: R42.2 U7.17(CPEN) U8.4(EN)
NetC57_1: C57.1 D2.2(ANODE) R36.1 U7.27(RESETB)
NetC58_2: C58.2 U7.20(VDD33)
NetC59_2: C59.2 R38.2 U7.26(REFCLK) Y3.1
NetC60_2: C60.2 R38.1 U7.25(XO) Y3.3
NetC230_1: C230.1 C231.1 U18.34(PLLFILT)
NetC232_1: C232.1 C233.1 U18.14(CRFILT)
NetC234_2: C234.2 R157.1 U18.33(XTALIN/CLKIN) Y8.3
NetC235_2: C235.2 R157.2 U18.32(XTALOUT) Y8.1
NetC236_1: C236.1 D3.2(ANODE) R153.1 U18.26(RESET_N)
NetR37_2: R37.2 U7.1(CLKOUT)
NetR39_2: R39.2 U7.24(RBIAS)
NetR41_2: R41.2 U8.3(/OC)
NetR152_2: R152.2 U18.28(SUSP_IND/LOCAL_PWR/NON_REM0)
NetR154_2: R154.2 U18.22(SDA/SMBDATA/NON_REM1)
NetR155_2: R155.2 U18.24(SCL/SMBCLK/CFG_SEL0)
NetR156_2: R156.2 U18.25(HS_IND/CFG_SEL1)
NetR158_2: R158.2 U18.35(RBIAS)
NetR163_1: R163.1 U18.27(VBUS_DET)

Not connected (* = marked no-connect by the designer): U7 12(NC) 15(SPL_L) 16(SPK_R); U18 11(TEST) 12(PRTPWR1/BC_EN1) 13(OCSn1) 16(TPWR2/BC_EN2) 17(OCSn2) 18(TPWR3/BC_EN3) 19(OCSn3) 20(TPWR4/BC_EN4) 21(OCSn4)

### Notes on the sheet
- USB2.0 HOST PORT
- www.alinx.com
- ALINX Confidential

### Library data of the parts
C52-C62 C64 C223-C238 C241 C242 = CAP NP: VA: 电容
C63 = CAP POL: VA: 电容
D2 D3 = BZX84C36/SOT_0_Dup1: VA: 二极管
J5 J6 = DUAL USB: VA: 双层USB2.0接口
L26 L27 L29 L30 = INDUCTOR_Dup1: VA: 磁珠
R36-R42 R150-R158 R162 R163 = RESISTOR: VA: 电阻
U7 = USB3320C-EZK_6: VA: 芯片
U8 = TPS2051BDBV: VA: 芯片
U18 = USB2514_0: VA: 芯片
Y3 Y8 = X3_0_Dup1: VA: 无源晶振

## Sheet PAGE05 PS Ethernet1.SchDoc
size 386 x 279 mm
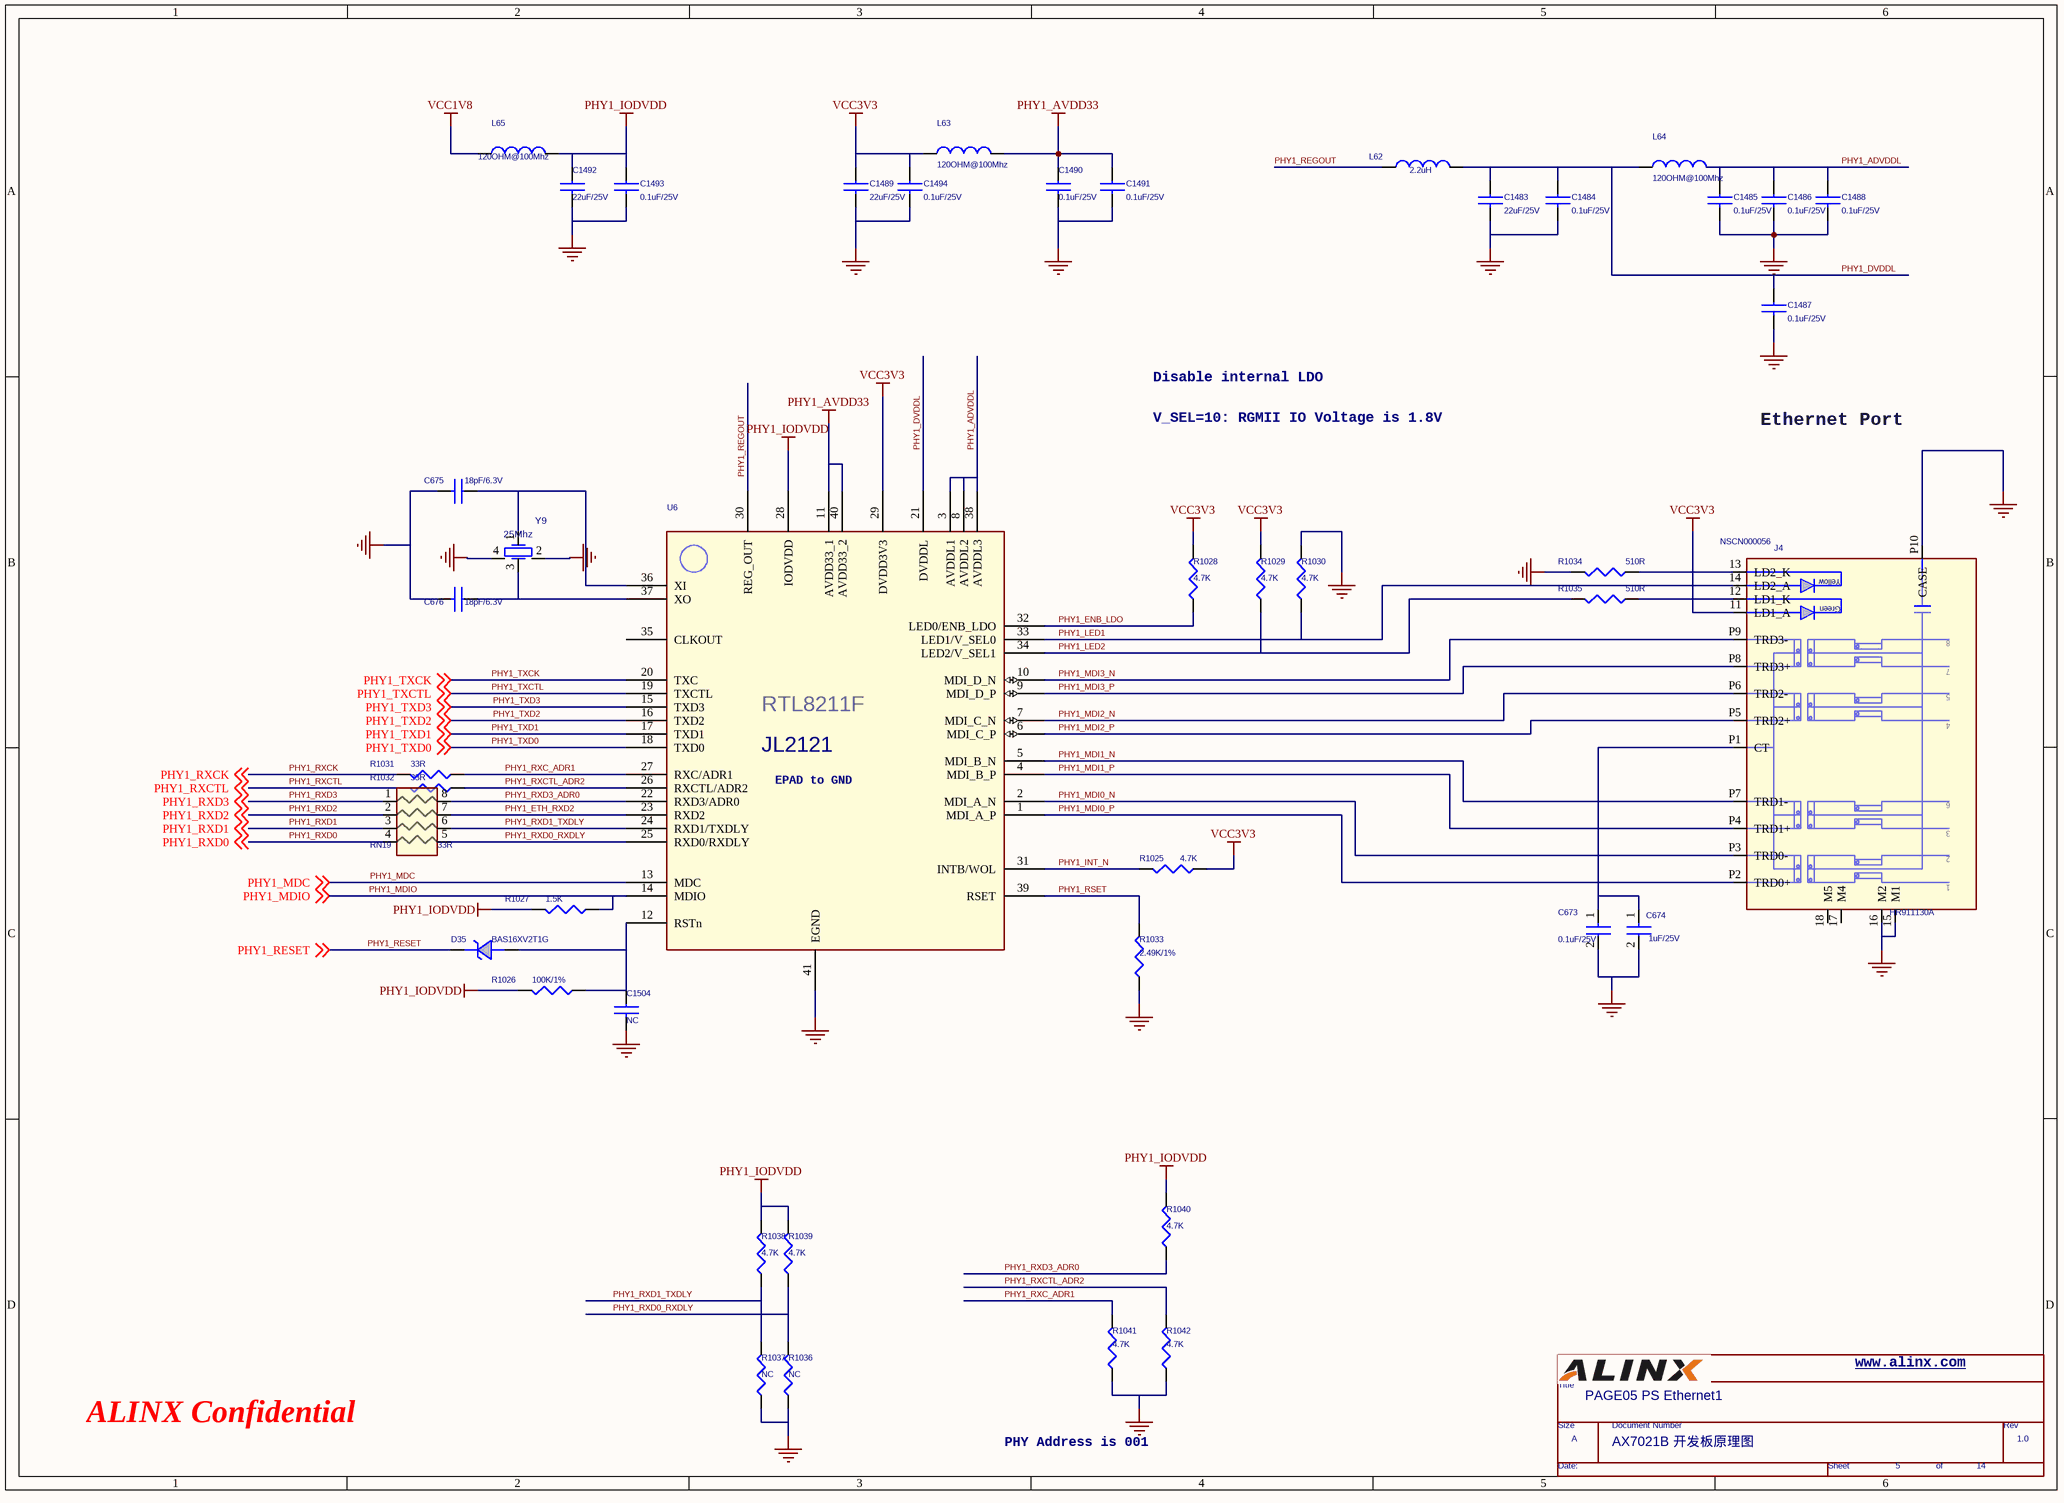
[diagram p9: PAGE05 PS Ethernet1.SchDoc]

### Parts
(Parts that share a designator on the sheet are numbered #1, #2 ... from top to bottom, then left to right.)
*#10  Doc: AX7021B 开发板原理图  RevCode: 1.0  Title: PAGE05 PS Ethernet1  Page Size: A  Page Number: 5  Page Count: 14  (hidden comment: TitleBlock0)  (graphical)
C673  0.1uF/25V  [C0402]
C674  1uF/25V  [C0402]
C675  18pF/6.3V  [C0402]
C676  18pF/6.3V  [C0402]
C1483  22uF/25V  [C0805]
C1484  0.1uF/25V  [C0402]
C1485  0.1uF/25V  [C0402]
C1486  0.1uF/25V  [C0402]
C1487  0.1uF/25V  [C0402]
C1488  0.1uF/25V  [C0402]
C1489  22uF/25V  [C0805]
C1490  0.1uF/25V  [C0402]
C1491  0.1uF/25V  [C0402]
C1492  22uF/25V  [C0805]
C1493  0.1uF/25V  [C0402]
C1494  0.1uF/25V  [C0402]
C1504  NC  [C0603]
D35  BAS16XV2T1G  [SOD-523]
J4  HR911130A  CODE: NSCN000056  [GE_RJ45]
L62  2.2uH  [LVS303010]
L63  120OHM@100Mhz  [L0603]
L64  120OHM@100Mhz  [L0603]
L65  120OHM@100Mhz  [L0603]
R1025  4.7K  [R0402]
R1026  100K/1%  [R0402]
R1027  1.5K  [R0402]
R1028  4.7K  [R0402]
R1029  4.7K  [R0402]
R1030  4.7K  [R0402]
R1031  33R  [R0402]
R1032  33R  [R0402]
R1033  2.49K/1%  [R0402]
R1034  510R  [R0402]
R1035  510R  [R0402]
R1036  NC  [R0402]
R1037  NC  [R0402]
R1038  4.7K  [R0402]
R1039  4.7K  [R0402]
R1040  4.7K  [R0402]
R1041  4.7K  [R0402]
R1042  4.7K  [R0402]
RN19  33R  [RN-8P]
U6  JL2121-N040I  [QFN40]  (value not drawn)
Y9  25Mhz  [OSC3225]

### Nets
GND: C673.2 C674.2 C675.2 C676.2 C1483.2 C1484.2 C1485.2 C1486.2 C1487.2 C1488.2 C1489.2 C1490.2 C1491.2 C1492.2 C1493.2 C1494.2 C1504.2 J4.15(M1) J4.16(M2) J4.P10(CASE) R1030.2 R1033.1 R1034.2 R1036.1 R1037.1 R1041.1 R1042.1 U6.41(EGND) Y9.2 Y9.4
PHY1_AVDD33: C1490.1 C1491.1 L63.2 U6.11(AVDD33_1) U6.40(AVDD33_2)
PHY1_IODVDD: C1492.1 C1493.1 L65.2 R1026.2 R1027.2 R1038.2 R1039.2 R1040.2 U6.28(IODVDD)
VCC1V8: L65.1
VCC3V3: C1489.1 C1494.1 J4.11(LD1_A) L63.1 R1025.1 R1028.2 R1029.2 U6.29(DVDD3V3)
PHY1_ADVDDL: C1485.1 C1486.1 C1488.1 L64.2 U6.3(AVDDL1) U6.8(AVDDL2) U6.38(AVDDL3)
PHY1_DVDDL: C1483.1 C1484.1 C1487.1 L62.2 L64.1 U6.21(DVDDL)
PHY1_ENB_LDO: R1028.1 U6.32(LED0/ENB_LDO)
PHY1_ETH_RXD2: RN19.7 U6.23(RXD2)
PHY1_INT_N: R1025.2 U6.31(INTB/WOL)
PHY1_LED1: J4.14(LD2_A) R1030.1 U6.33(LED1/V_SEL0)
PHY1_LED2: R1029.1 R1035.2 U6.34(LED2/V_SEL1)
PHY1_MDC: U6.13(MDC) ; off-sheet PHY1_MDC
PHY1_MDI0_N: J4.P3(TRD0-) U6.2(MDI_A_N)
PHY1_MDI0_P: J4.P2(TRD0+) U6.1(MDI_A_P)
PHY1_MDI1_N: J4.P7(TRD1-) U6.5(MDI_B_N)
PHY1_MDI1_P: J4.P4(TRD1+) U6.4(MDI_B_P)
PHY1_MDI2_N: J4.P6(TRD2-) U6.7(MDI_C_N)
PHY1_MDI2_P: J4.P5(TRD2+) U6.6(MDI_C_P)
PHY1_MDI3_N: J4.P9(TRD3-) U6.10(MDI_D_N)
PHY1_MDI3_P: J4.P8(TRD3+) U6.9(MDI_D_P)
PHY1_MDIO: R1027.1 U6.14(MDIO) ; off-sheet PHY1_MDIO
PHY1_REGOUT: L62.1 U6.30(REG_OUT)
PHY1_RESET: D35.1(CATHODE) ; off-sheet PHY1_RESET
PHY1_RSET: R1033.2 U6.39(RSET)
PHY1_RXC_ADR1: R1031.1 R1041.2 U6.27(RXC/ADR1)
PHY1_RXCK: R1031.2 ; off-sheet PHY1_RXCK
PHY1_RXCTL: R1032.2 ; off-sheet PHY1_RXCTL
PHY1_RXCTL_ADR2: R1032.1 R1042.2 U6.26(RXCTL/ADR2)
PHY1_RXD0: RN19.4 ; off-sheet PHY1_RXD0
PHY1_RXD0_RXDLY: R1036.2 R1039.1 RN19.5 U6.25(RXD0/RXDLY)
PHY1_RXD1: RN19.3 ; off-sheet PHY1_RXD1
PHY1_RXD1_TXDLY: R1037.2 R1038.1 RN19.6 U6.24(RXD1/TXDLY)
PHY1_RXD2: RN19.2 ; off-sheet PHY1_RXD2
PHY1_RXD3: RN19.1 ; off-sheet PHY1_RXD3
PHY1_RXD3_ADR0: R1040.1 RN19.8 U6.22(RXD3/ADR0)
PHY1_TXCK: U6.20(TXC) ; off-sheet PHY1_TXCK
PHY1_TXCTL: U6.19(TXCTL) ; off-sheet PHY1_TXCTL
PHY1_TXD0: U6.18(TXD0) ; off-sheet PHY1_TXD0
PHY1_TXD1: U6.17(TXD1) ; off-sheet PHY1_TXD1
PHY1_TXD2: U6.16(TXD2) ; off-sheet PHY1_TXD2
PHY1_TXD3: U6.15(TXD3) ; off-sheet PHY1_TXD3
NetC673_1: C673.1 C674.1 J4.P1(CT)
NetC675_1: C675.1 U6.36(XI) Y9.1
NetC676_1: C676.1 U6.37(XO) Y9.3
NetC1504_1: C1504.1 D35.2(ANODE) R1026.1 U6.12(RSTn)
NetJ4_12: J4.12(LD1_K) R1035.1
NetJ4_13: J4.13(LD2_K) R1034.1

Not connected (* = marked no-connect by the designer): J4 17(M4) 18(M5); U6 35(CLKOUT)

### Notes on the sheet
- Disable internal LDO
- V_SEL=10: RGMII IO Voltage is 1.8V
- Ethernet Port
- www.alinx.com
- ALINX Confidential
- PHY Address is 001

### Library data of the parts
C673 = CAP_3: as C1562 on sheet PAGE11 PL Ethernet5
C674 = CAP_3: as C1563 on sheet PAGE11 PL Ethernet5
C675 C676 C1483-C1494 = CAP NP: VA: 电容
C1504 = CAP NP
D35 = BZX84C36/SOT_0: VA: 二极管
J4 = GE_RJ45_2: VA: 网口插件
L62 = INDUCTOR_Dup1: VA: 电感
L63-L65 = INDUCTOR_Dup1: VA: 磁珠
R1025-R1035 R1038-R1042 = RESISTOR: VA: 电阻
R1036 R1037 = RESISTOR
RN19 = RESARR_IS_4/SM: VA: 排阻
U6 = JL2121D-N040I_0: VA: 芯片
Y9 = X3_0: VA: 无源晶振

## Sheet PAGE04 SD Card and UART.SchDoc
size 386 x 279 mm
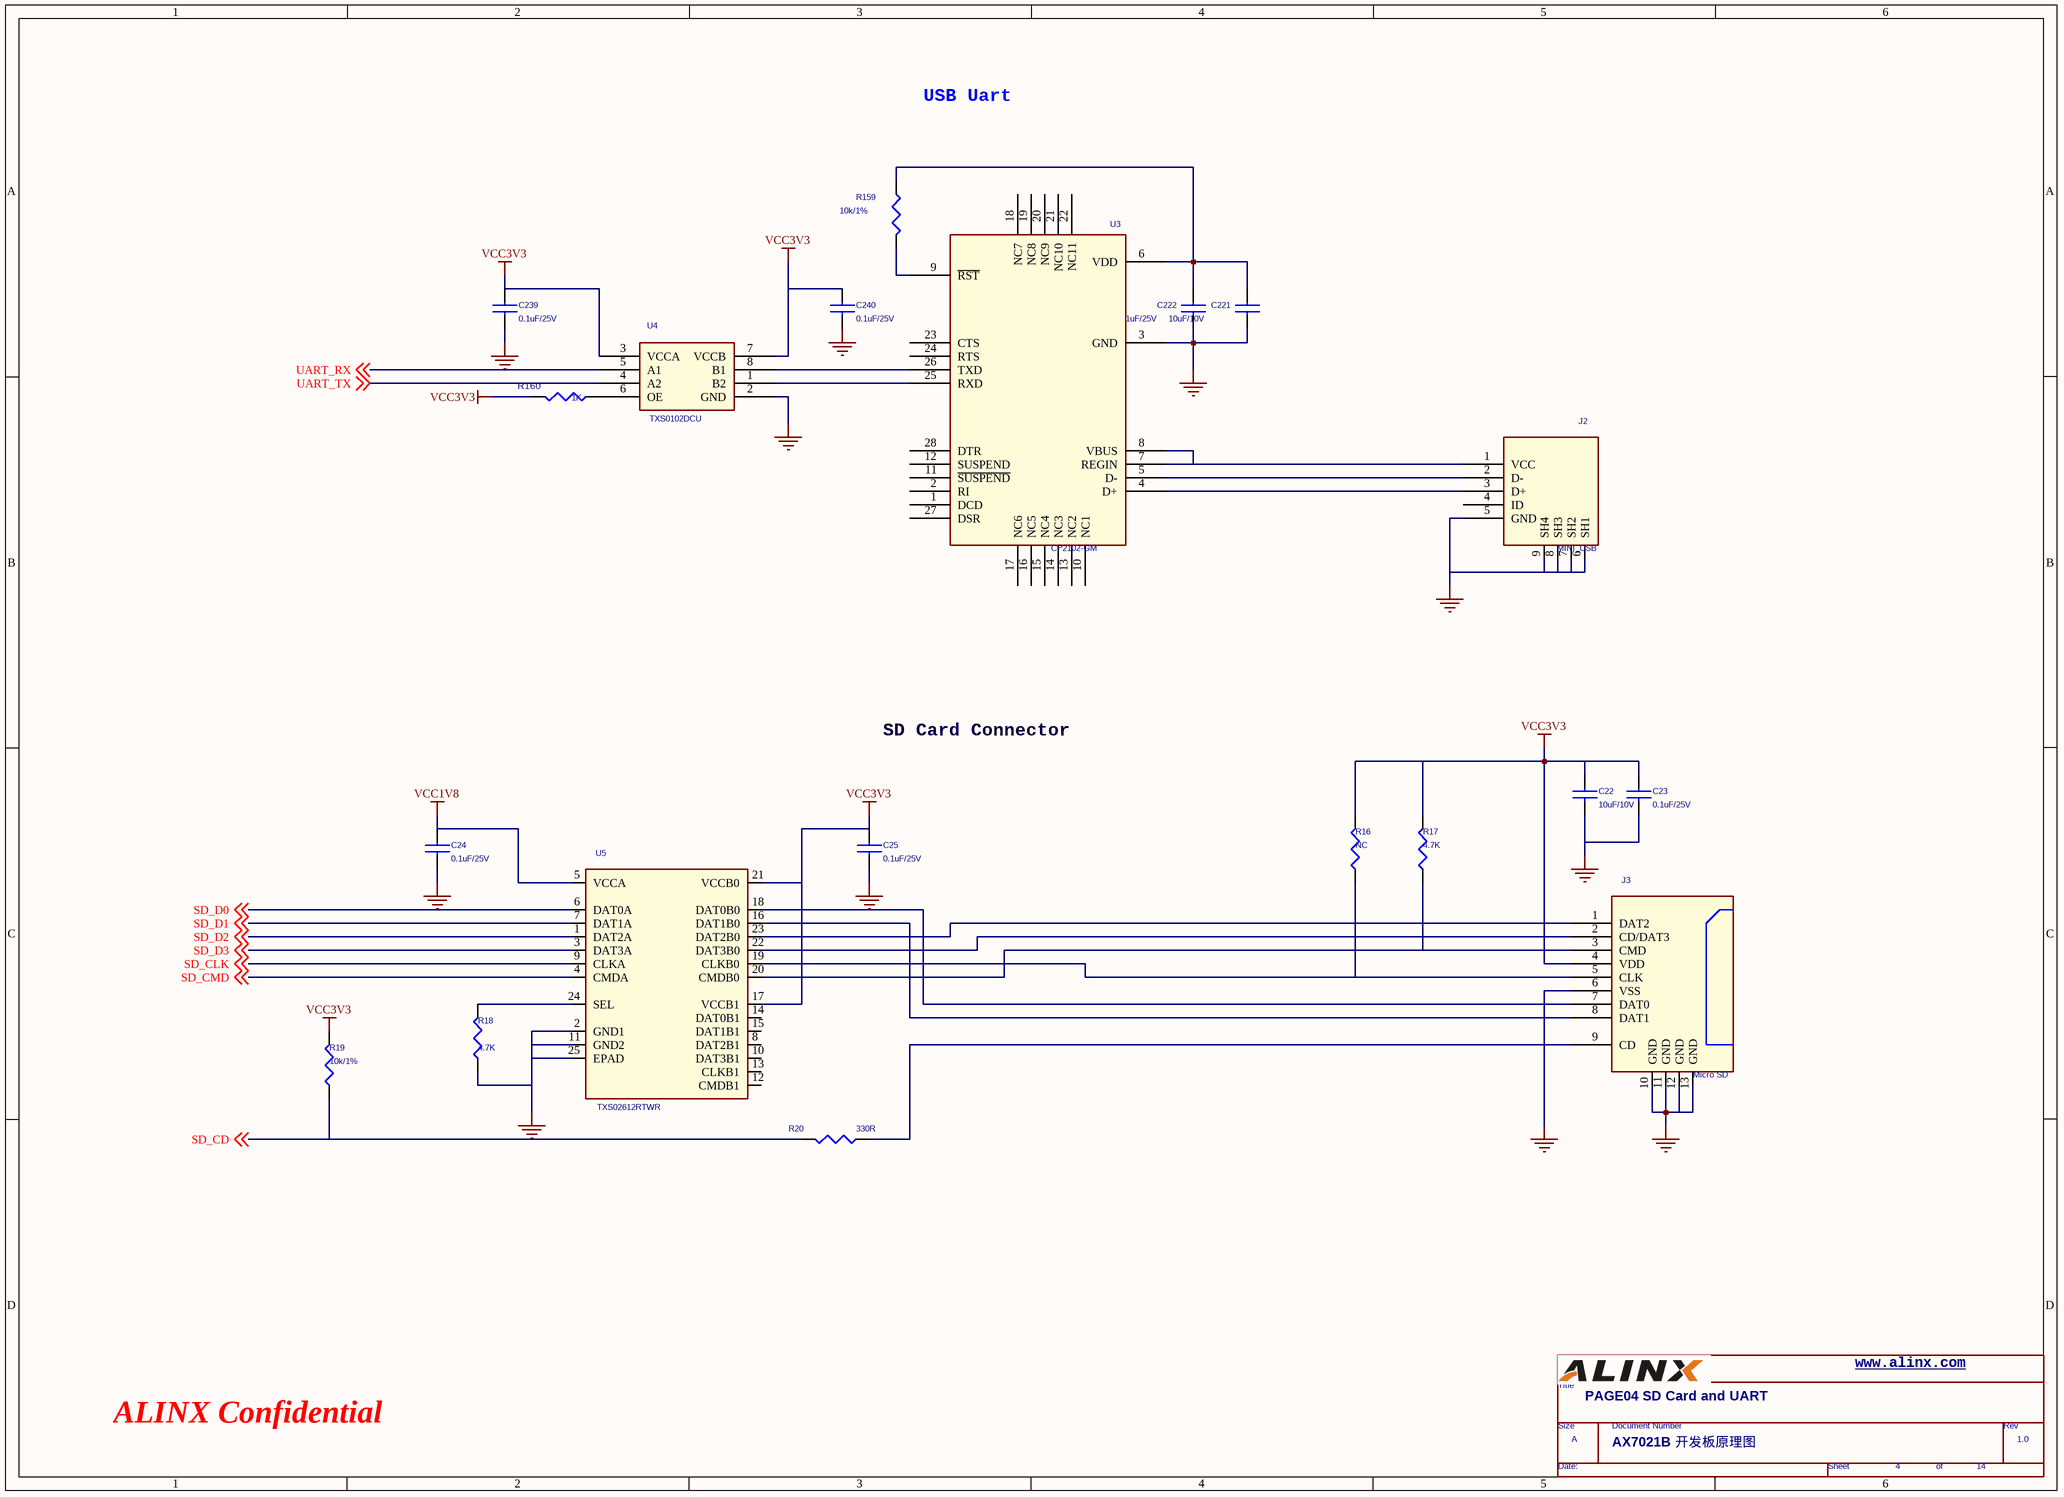
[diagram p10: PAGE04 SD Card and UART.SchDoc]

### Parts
(Parts that share a designator on the sheet are numbered #1, #2 ... from top to bottom, then left to right.)
*#11  Doc: AX7021B 开发板原理图  RevCode: 1.0  Title: PAGE04 SD Card and UART  Page Size: A  Page Number: 4  Page Count: 14  (hidden comment: TitleBlock0)  (graphical)
C22  10uF/10V  [C0603]
C23  0.1uF/25V  [C0402]
C24  0.1uF/25V  [C0402]
C25  0.1uF/25V  [C0402]
C221  10uF/10V  [C0603]
C222  1uF/25V  [C0402]
C239  0.1uF/25V  [C0402]
C240  0.1uF/25V  [C0402]
J2  MINI_USB  [mini_usb_dip]
J3  Micro SD  [Micro_usb]
R16  NC  [R0402]
R17  4.7K  [R0402]
R18  4.7K  [R0402]
R19  10k/1%  [R0402]
R20  330R  [R0402]
R159  10k/1%  [R0402]
R160  1K  [R0402]
U3  CP2102-GM  [QFN-28]
U4  TXS0102DCU  [vssop8]
U5  TXS02612RTWR  [QFN24_RTW]

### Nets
EPAD1: U3.29(EPAD1)
EPAD2: U3.30(EPAD2)
GND: C22.2 C23.2 C24.2 C25.2 C221.2 C222.2 C239.2 C240.2 J2.5(GND) J2.6(SH1) J2.7(SH2) J2.8(SH3) J2.9(SH4) J3.6(VSS) J3.10(GND) J3.11(GND) J3.12(GND) J3.13(GND) R18.1 U3.3(GND) U4.2(GND) U5.2(GND1) U5.11(GND2) U5.25(EPAD)
VCC1V8: C24.1 U5.5(VCCA)
VCC3V3: C22.1 C23.1 C25.1 C239.1 C240.1 J3.4(VDD) R16.2 R17.2 R19.2 R160.1 U4.3(VCCA) U4.7(VCCB) U5.17(VCCB1) U5.21(VCCB0)
SD_CD: R19.1 R20.2 ; off-sheet SD_CD
SD_CLK: U5.9(CLKA) ; off-sheet SD_CLK
SD_CMD: U5.4(CMDA) ; off-sheet SD_CMD
SD_D0: U5.6(DAT0A) ; off-sheet SD_D0
SD_D1: U5.7(DAT1A) ; off-sheet SD_D1
SD_D2: U5.1(DAT2A) ; off-sheet SD_D2
SD_D3: U5.3(DAT3A) ; off-sheet SD_D3
UART_RX: U4.5(A1) ; off-sheet UART_RX
UART_TX: U4.4(A2) ; off-sheet UART_TX
NetC221_1: C221.1 C222.1 R159.2 U3.6(VDD)
NetJ2_1: J2.1(VCC) U3.7(REGIN) U3.8(VBUS)
NetJ2_2: J2.2(D-) U3.5(D-)
NetJ2_3: J2.3(D+) U3.4(D+)
NetJ3_1: J3.1(DAT2) U5.23(DAT2B0)
NetJ3_2: J3.2(CD/DAT3) U5.22(DAT3B0)
NetJ3_3: J3.3(CMD) R17.1 U5.20(CMDB0)
NetJ3_5: J3.5(CLK) R16.1 U5.19(CLKB0)
NetJ3_7: J3.7(DAT0) U5.18(DAT0B0)
NetJ3_8: J3.8(DAT1) U5.16(DAT1B0)
NetJ3_9: J3.9(CD) R20.1
NetR18_2: R18.2 U5.24(SEL)
NetR159_1: R159.1 U3.9(~{RST})
NetR160_2: R160.2 U4.6(OE)
NetU3_25: U3.25(RXD) U4.1(B2)
NetU3_26: U3.26(TXD) U4.8(B1)

Not connected (* = marked no-connect by the designer): J2 4(ID); U3 1(DCD) 2(RI) 10(NC1) 11(~{SUSPEND}) 12(SUSPEND) 13(NC2) 14(NC3) 15(NC4) 16(NC5) 17(NC6) 18(NC7) 19(NC8) 20(NC9) 21(NC10) 22(NC11) 23(CTS) 24(RTS) 27(DSR) 28(DTR); U5 8(DAT2B1) 10(DAT3B1) 12(CMDB1) 13(CLKB1) 14(DAT0B1) 15(DAT1B1)

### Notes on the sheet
- USB Uart
- SD Card Connector
- www.alinx.com
- ALINX Confidential

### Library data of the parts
C22-C25 C221 C222 C239 C240 = CAP NP: VA: 电容
J2 = USB_B_3: VA: 直插USB接口
J3 = Micro SD_1: VA: SD卡座
R16 = RESISTOR
R17-R20 R159 = RESISTOR: VA: 电阻
R160 = RESISTOR_0: VA: 电阻
U3 = CP2102_2: VA: 芯片
U4 = TXS0102DCU_1: VA: 芯片
U5 = TXS02612RTWR_0: VA: 芯片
